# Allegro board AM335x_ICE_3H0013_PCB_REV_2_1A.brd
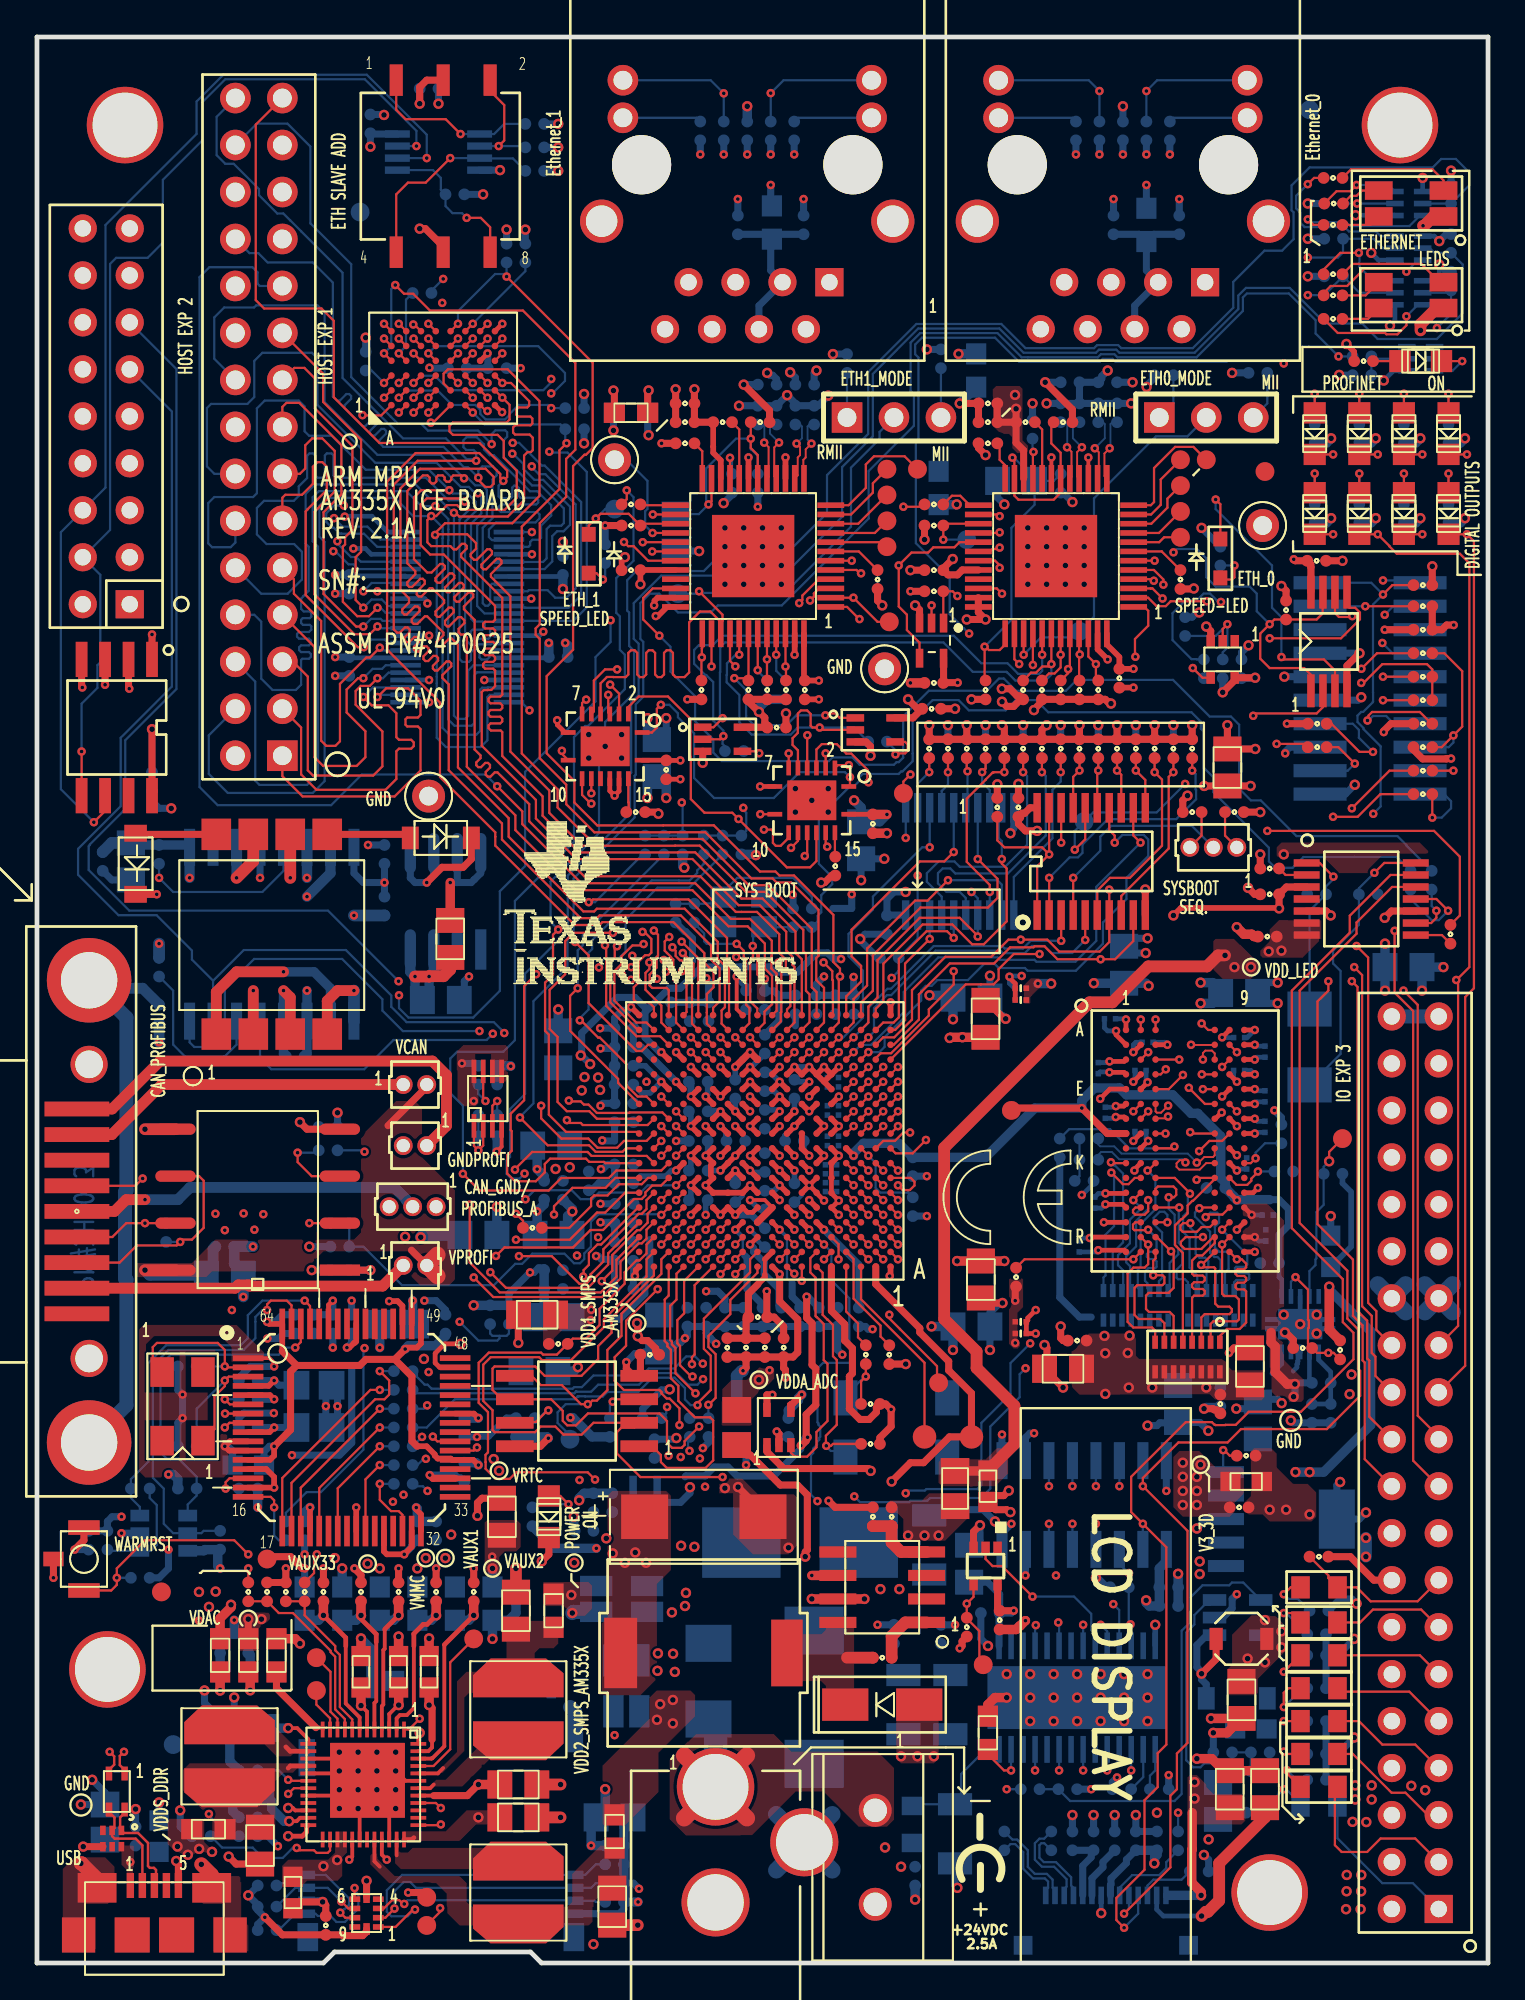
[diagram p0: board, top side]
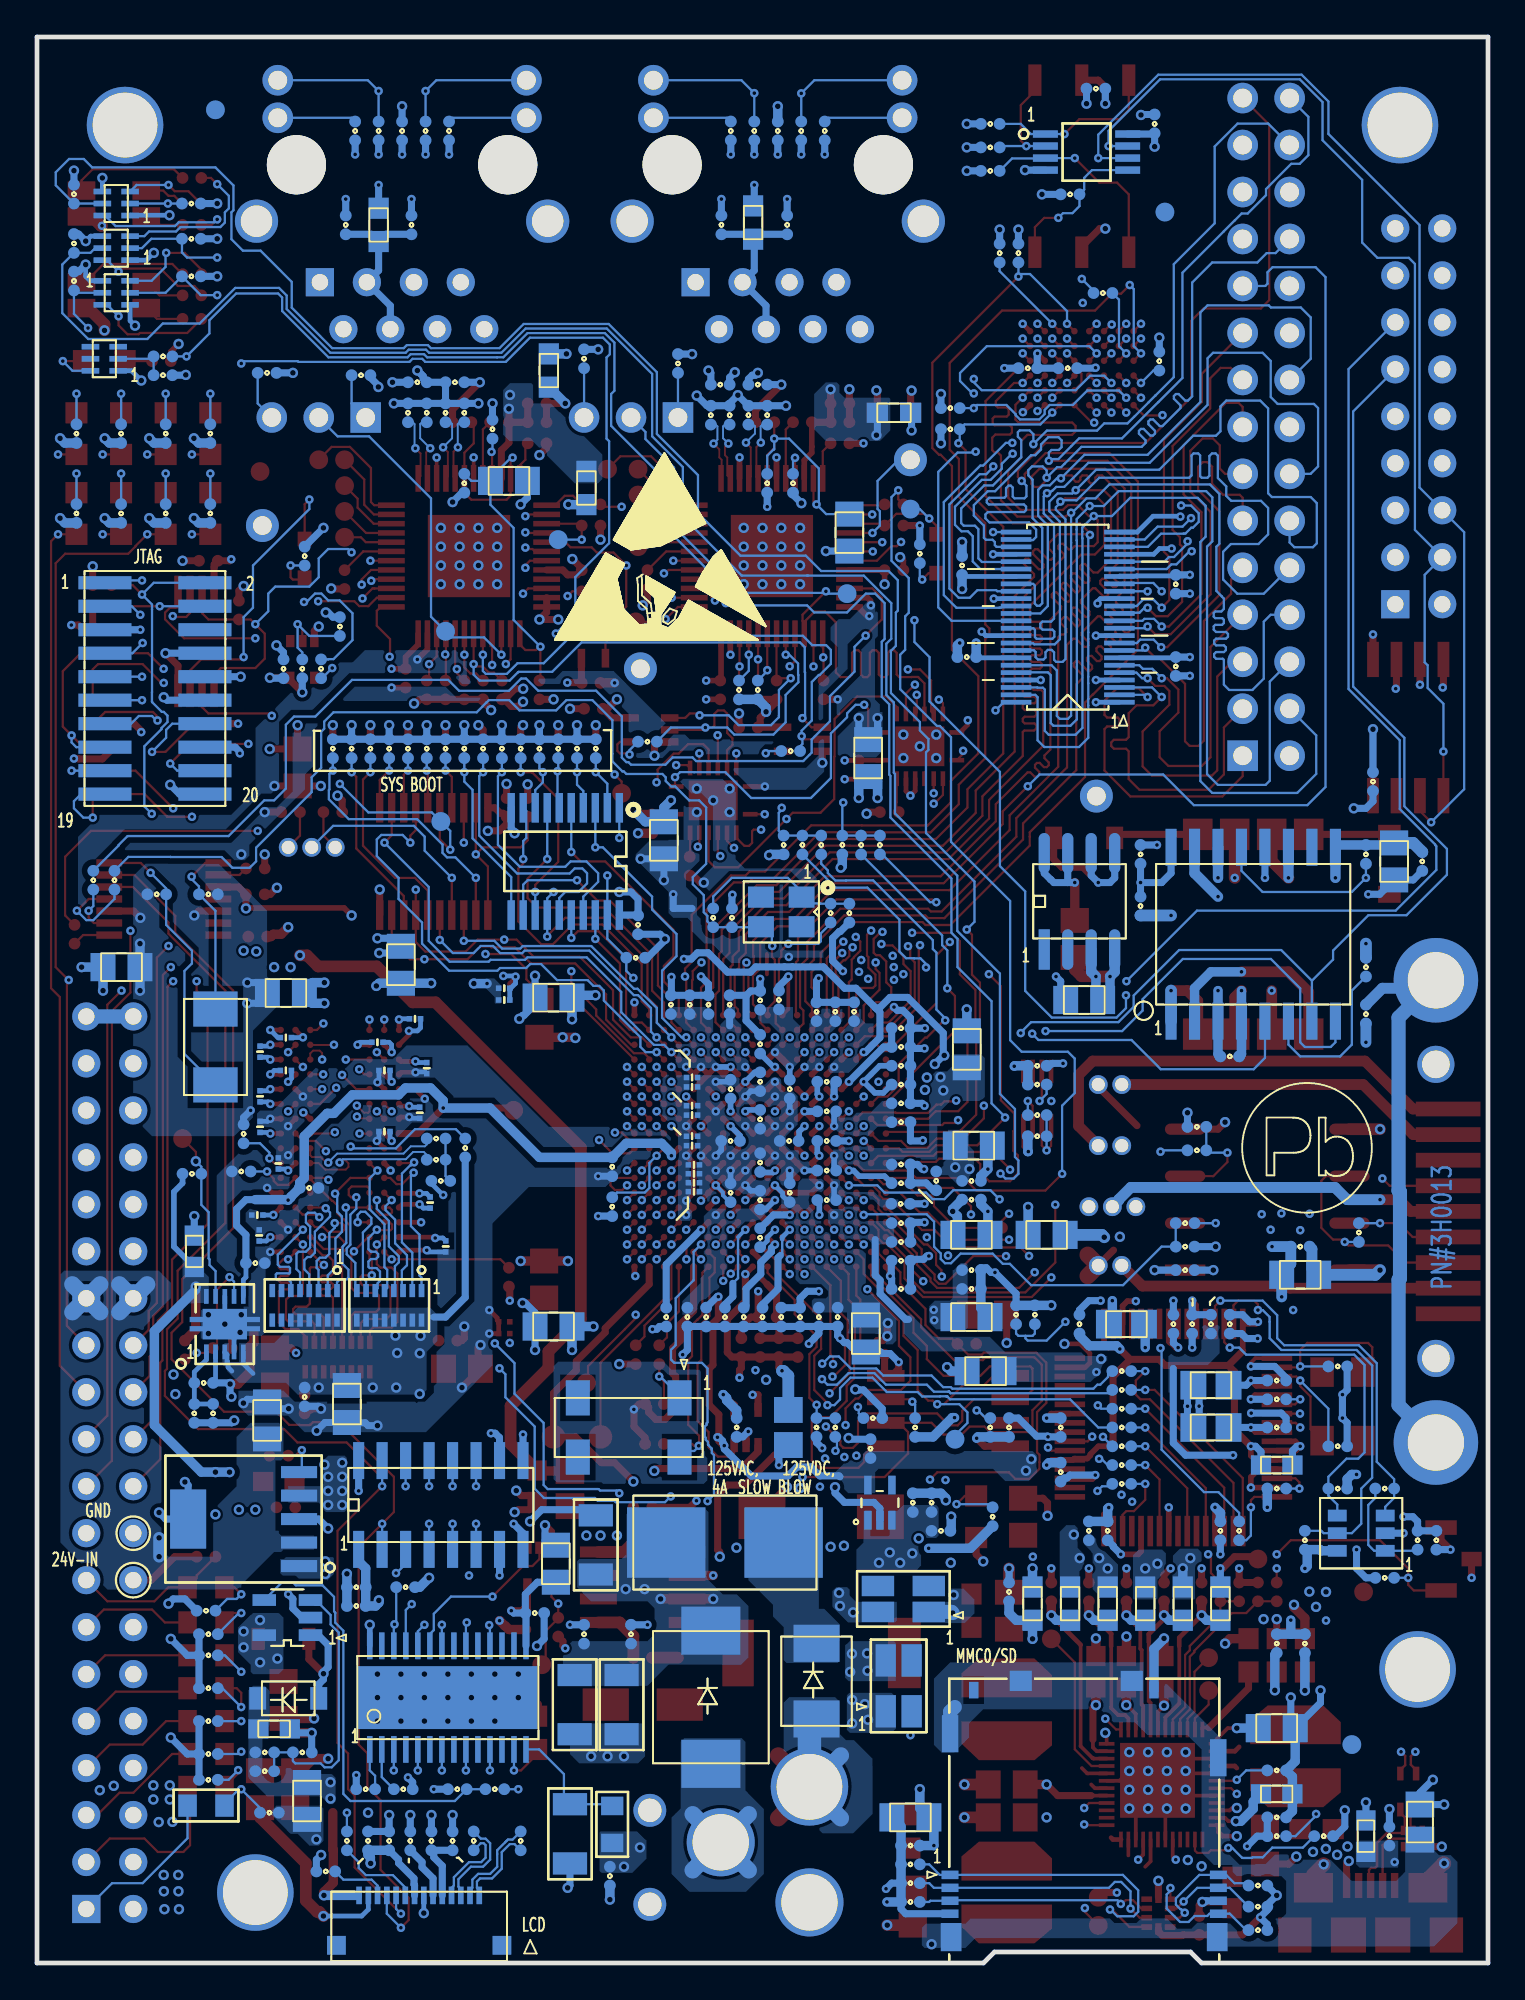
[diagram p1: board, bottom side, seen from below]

Outline 78.49 x 104.14 mm; copper layers: TOP, LYR2_GND, LYR3, LYR4, LYR5_PWR, BOTTOM. Coordinates in mm from the lower left corner of the outline.
Outline path: 0,104.14 0,0 15.49,0 16.09,0.6 26.7,0.6 27.29,0 78.49,0 78.49,104.14 0,104.14

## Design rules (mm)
net group C1: nets C1N C1P
net group C2: nets C2N C2P
net group MMC0_CLK: nets MMC0_CLK N28737675
net group PR_CLK: nets PR1_MDIO_MDCLK PR1_MII1_CLK
net group PRUETHER0_RD: nets PRUETHER0_RDN PRUETHER0_RDP
net group PRUETHER0_TD: nets PRUETHER0_TDN PRUETHER0_TDP
net group PRUETHER1_RD: nets PRUETHER1_RDN PRUETHER1_RDP
net group PRUETHER1_TD: nets PRUETHER1_TDN PRUETHER1_TDP
net group USB: nets USBDM USBDP
net group USB_FT: nets USBDM_FT USBDP_FT
net group 3W: nets CAN0_H CAN0_L PROFIBUS_A PROFIBUS_B SYS_RESETN UART0_RXD UART0_TXD UART1_RXD UART1_TXD UART3_RXD UART3_TXD
net group AIN: nets AIN1 AIN2 AIN3 AIN4 AIN5 AIN6 AIN7
net group CLK: nets AM335X_OSC0_IN AM335X_REFCLK_RMII1 AM335X_REFCLK_RMII2 ETH0_CLKIN ETH1_CLKIN MDIO_CLK OSC0_OUT OSC0_OUT1 OSC1_IN OSC1_OUT OSC1_OUT1 PRUETH0_RXCLK PRUETH0_TXCLK SPI0_SCLK SPI1_SCLK SYS_BOOT0 SYS_BOOT14 XTIN XTOUT
net group ETH_0: nets B_PRUETH0_LINKLED PRUETH0_ACTLED PRUETH0_COL PRUETH0_INT PRUETH0_JTCK PRUETH0_JTDI PRUETH0_JTDO PRUETH0_JTMS PRUETH0_JTRSTN PRUETH0_RESETN PRUETH0_RXERR PRUETH0_RXERR_COL PRUETH0_RXERR_COL_PROC PRUETH0_SPEEDLED PRUETH0_SWSTRAP
net group ETH_1: nets PRUETH1_ACTLED PRUETH1_COL PRUETH1_INTN PRUETH1_JTCK PRUETH1_JTDI PRUETH1_JTDO PRUETH1_JTMS PRUETH1_JTRSTN PRUETH1_RXD3 PRUETH1_RXDV PRUETH1_SPEEDLED PRUETH1_SWSTRAP PRUETH1_TXCLK PRUETH1_TXD0 PRUETH1_TXEN
net group GPMC_AD: nets GPMC_CSN0
net group PR1_MII0: nets PR1_MII0_RXLINK_SPEED PRUETH0_CRS PRUETH0_RXD0 PRUETH0_RXD1 PRUETH0_RXD2 PRUETH0_RXD3 PRUETH0_RXDV PRUETH0_TXD0 PRUETH0_TXD1 PRUETH0_TXD2 PRUETH0_TXD3 PRUETH0_TXEN SYS_BOOT1 SYS_BOOT2 SYS_BOOT3 SYS_BOOT4 SYS_BOOT5 SYS_BOOT6 SYS_BOOT7 SYS_BOOT8 SYS_BOOT9 SYS_BOOT10 SYS_BOOT11 SYS_BOOT12 SYS_BOOT13 SYS_BOOT15
net group PR1_MII1: nets PR1_MII1_COL_RMII2_CRS_DV PR1_MII1_CRS PRUETH1_LINKLED
net group PRUETH1_RXERR: nets PRUETH1_RXERR_COL
net group PWR: nets AGND_CAN AGND_PRUETH0 AGND_PRUETH1 AGNDFRAME_PRUETH0 AGNDFRAME_PRUETH1 BOOT CAN_GND/PROFIBUS_A CAP_VBB_MPU CAP_VDD_SRAM_CORE CAP_VDD_SRAM_MPU DDR_VREF GND_OSC0 GND_OSC1 GNDA_ADC GNDPROFI N17123334 N17123833 N21868977 N27955689 PROFI_GND PWR_SWIO PWR_VAUX1 PWR_VAUX2 PWR_VAUX33 PWR_VDAC PWR_VDD1_SMPS PWR_VDD2_SMPS PWR_VDDIO PWR_VDDS_DDR PWR_VDIG1 PWR_VDIG2 PWR_VMMC PWR_VPLL PWRON SENSE V3_3D_PROFIA V3_3D_PROFIB V3_3D_PRUETH0JCK V3_3D_PRUETH1JCK V5_0VOP VBAT_LCD VBREF VCOMH VDD_1V8FT VDD_FTREGIN VDD_FTVPHY VDD_FTVPLL VDD_RTC VDIG1 VPLL VPMIC_VRTC VPP VREFP_ADC
nets with their own width: min track width 0.305; nets VAUX1 VAUX33 VDD_LED VRTC

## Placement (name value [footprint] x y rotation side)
C1  0.01uF  [SM-7351-CAP-0402]  35.05 84.33 180 top
C2  0.01uF  [SM-7351-CAP-0402]  51.44 84.33 180 top
C3  0.01uF  [SM-7351-CAP-0402]  35.05 83.31 180 top
C4  0.1uF  [SM-7351-CAP-0402]  39.12 83.31 0 top
C5  0.01uF  [SM-7351-CAP-0402]  51.44 83.31 180 top
C6  0.1uF  [SM-7351-CAP-0402]  55.5 83.31 0 top
C7  0.1uF  [SM-7351-CAP-0402]  69.22 75.82 0 top
C8  0.01uF  [SM-7351-CAP-0402]  74.96 72.09 0 top
C9  0.01uF  [SM-7351-CAP-0402]  32.13 75.31 180 top
C10  0.01uF  [SM-7351-CAP-0402]  48.51 75.31 180 top
C11  0.01uF  [SM-7351-CAP-0402]  58.55 69.47 270 top
C12  0.01uF  [SM-7351-CAP-0402]  48.51 69.22 180 top
C13  0.1uF  [SM-7351-CAP-0402]  74.96 65.74 180 top
C14  0.1uF  [SM-7351-CAP-0402]  35.94 68.83 270 top
C15  0.01uF  [SM-7351-CAP-0402]  41.53 68.83 270 top
C16  0.1uF  [SM-7351-CAP-0402]  51.31 68.83 270 top
C17  0.1uF  [SM-7351-CAP-0402]  48.39 67.82 0 top
C18  0.1uF  [SM-7351-CAP-0402]  40.01 66.8 0 top
C19  0.1uF  [SM-7351-CAP-0402]  34.04 64.52 270 top
C20  0.1uF  [SM-7351-CAP-0402]  45.21 61.59 270 top
C21  0.1uF  [SM-7351-CAP-0402]  66.67 57.78 180 top
C22  0.1uF  [SM-7351-CAP-0402]  66.55 55.5 180 top
C23  10uF  [SM-7351-CAP-0805]  64.39 64.64 270 top
C24  4.7uF  [SM-7351-CAP-0805]  22.35 55.37 270 top
C25  0.1uF, 6.3V  [SMD0201]  53.21 52.7 0 top
C26  0.1uF, 6.3V  [SMD0201]  53.21 52.07 0 top
C27  10uF  [SM-7351-CAP-0805]  51.31 51.05 90 top
C28  10uF  [SM-7351-CAP-0805]  51.05 36.96 270 top
C29  10uF  [SM-7351-CAP-0805]  27.05 35.05 180 top
C30  0.1uF, 6.3V  [SMD0201]  53.21 34.67 0 top
C31  0.1uF, 6.3V  [SMD0201]  53.21 34.04 0 top
C32  0.1uF  [SM-7351-CAP-0402]  56.26 33.66 180 top
C33  0.001uF  [SM-7351-CAP-0402]  37.34 33.27 270 top
C34  0.01uF  [SM-7351-CAP-0402]  38.35 33.27 270 top
C35  0.01uF  [SM-7351-CAP-0402]  39.37 33.27 270 top
C36  0.01uF  [SM-7351-CAP-0402]  40.39 33.27 270 top
C37  0.01uF  [SM-7351-CAP-0402]  33.15 32.89 180 top
C38  10uF  [SM-7351-CAP-0805]  65.61 32.26 90 top
C39  10uF  [SM-7351-CAP-0805]  55.5 32.13 180 top
C40  22pF  [SM-7351-CAP-0402]  45.09 30.23 180 top
C41  0.1uF  [SM-7351-CAP-0402]  64.01 30.23 270 top
C42  22pF  [SM-7351-CAP-0402]  45.09 28.07 180 top
C43  0.01uF  [SM-7351-CAP-0402]  65.41 27.43 0 top
C44  4.7uF  [SM-7351-CAP-0603]  65.41 26.04 0 top
C45  4.7uF  [SM-7351-CAP-0603]  51.44 25.78 270 top
C46  0.01uF  [SM-7351-CAP-0402]  65.02 24.64 0 top
C47  10uF  [SM-7351-CAP-0805]  25.15 24.13 90 top
C48  47uF  [7343]  36.07 24.13 0 top
C49  2.2uF  [SM-7351-CAP-0402]  15.49 20.07 90 top
C50  2.2uF  [SM-7351-CAP-0402]  17.53 20.07 90 top
C51  2.2uF, 10V  [SM-7351-CAP-0402]  19.56 20.07 90 top
C52  2.2uF, 10V  [SM-7351-CAP-0402]  21.59 20.07 90 top
C53  2.2uF  [SM-7351-CAP-0402]  23.62 20.07 90 top
C54  10uF  [SM-7351-CAP-0805]  25.91 19.05 90 top
C55  0.1uF  [SM-7351-CAP-0402]  52.07 18.54 270 top
C56  0.01uF  [SM-7351-CAP-0402]  45.72 16.51 180 top
C57  4.7uF  [SM-7351-CAP-0603]  17.53 15.75 90 top
C58  4.7uF  [SM-7351-CAP-0603]  19.56 15.75 90 top
C59  4.7uF  [SM-7351-CAP-0603]  21.21 15.75 90 top
C60  2.2uF  [SM-7351-CAP-0805]  65.15 14.22 270 top
C61  10uF  [SM-7351-CAP-0805]  26.04 9.65 0 top
C62  2.2uF  [SM-7351-CAP-0805]  64.52 9.4 90 top
C63  2.2uF  [SM-7351-CAP-0805]  66.42 9.4 90 top
C64  10uF  [SM-7351-CAP-0805]  26.04 7.87 0 top
C65  10uF  [SM-7351-CAP-0805]  12.06 6.35 270 top
C66  4.7uF  [SM-7351-CAP-0603]  13.84 3.81 270 top
C67  10uF  [SM-7351-CAP-0805]  31.11 3.05 270 top
C68  0.01uF  [SM-7351-CAP-0402]  15.62 2.03 90 top
C69  0.01uF  [SM-7351-CAP-0402]  21.21 101.35 0 bottom
C70  0.1uF  [SM-7351-CAP-0402]  18.03 99.44 90 bottom
C71  0.1uF  [SM-7351-CAP-0402]  61.79 93.98 90 bottom
C72  0.1uF  [SM-7351-CAP-0402]  58.23 93.98 90 bottom
C73  0.1uF  [SM-7351-CAP-0402]  41.47 93.98 90 bottom
C74  0.1uF  [SM-7351-CAP-0402]  37.91 93.98 90 bottom
C75  0.1uF  [SM-7351-CAP-0402]  24.89 86.23 0 bottom
C76  1uF  [SM-7351-CAP-0402]  22.73 86.23 180 bottom
C77  0.1uF  [SM-7351-CAP-0402]  57.91 85.47 0 bottom
C78  0.1uF  [SM-7351-CAP-0402]  55.88 85.47 180 bottom
C79  0.1uF  [SM-7351-CAP-0402]  41.53 85.34 0 bottom
C80  0.1uF  [SM-7351-CAP-0402]  39.5 85.34 180 bottom
C81  10uF  [SM-7351-CAP-0805]  52.96 80.14 180 bottom
C82  0.1uF  [SM-7351-CAP-0402]  55.37 80.01 270 bottom
C83  0.1uF  [SM-7351-CAP-0402]  38.99 80.01 270 bottom
C84  10uF  [SM-7351-CAP-0805]  34.54 77.34 270 bottom
C85  0.1uF  [SM-7351-CAP-0402]  28.45 75.56 90 bottom
C86  0.1uF  [SM-7351-CAP-0402]  16.89 74.55 270 bottom
C87  0.1uF  [SM-7351-CAP-0402]  28.19 70.61 0 bottom
C88  0.1uF  [SM-7351-CAP-0402]  16.89 70.1 270 bottom
C89  18pF, 50V  [SM-7351-CAP-0402]  72.01 57.78 180 bottom
C90  18pF, 50V  [SM-7351-CAP-0402]  69.22 57.78 0 bottom
C91  0.1uF  [SM-7351-CAP-0402]  65.15 69.98 90 bottom
C92  10uF  [SM-7351-CAP-0805]  33.53 65.15 90 bottom
C93  0.1uF  [SM-7351-CAP-0402]  6.22 63.88 270 bottom
C94  10uF  [SM-7351-CAP-0805]  44.58 60.71 270 bottom
C95  10uF  [SM-7351-CAP-0805]  5.08 59.56 90 bottom
C96  0.1uF  [SM-7351-CAP-0402]  3.56 59.56 90 bottom
C97  2.2uF  [SM-7351-CAP-0805]  73.91 53.85 180 bottom
C98  0.01uF  [SM-7351-CAP-0402]  18.8 57.15 270 bottom
C99  24pF  [SM-7351-CAP-0402]  34.54 56.77 270 bottom
C100  24pF  [SM-7351-CAP-0402]  40.89 56.52 90 bottom
C101  10uF  [SM-7351-CAP-0805]  58.8 53.98 90 bottom
C102  10uF  [SM-7351-CAP-0805]  65.02 52.45 0 bottom
C103  0.1uF, 6.3V  [SMD0201]  53.21 52.7 0 bottom
C104  10uF  [SM-7351-CAP-0805]  50.55 52.2 0 bottom
C105  0.1uF, 6.3V  [SMD0201]  53.21 52.07 0 bottom
C106  0.01uF  [SM-7351-CAP-0402]  38.35 52.07 90 bottom
C107  10uF  [SM-7351-CAP-0805]  21.84 52.07 180 bottom
C108  0.01uF  [SM-7351-CAP-0402]  39.37 52.05 90 bottom
C109  0.01uF  [SM-7351-CAP-0402]  44.2 51.82 270 bottom
C110  0.01uF  [SM-7351-CAP-0402]  43.18 51.82 270 bottom
C111  0.01uF  [SM-7351-CAP-0402]  42.16 51.82 270 bottom
C112  0.01uF  [SM-7351-CAP-0402]  36.32 51.44 90 bottom
C113  0.01uF  [SM-7351-CAP-0402]  35.31 51.44 90 bottom
C114  0.01uF  [SM-7351-CAP-0402]  34.29 51.44 90 bottom
C115  0.1uF, 6.3V  [SMD0201]  58.04 51.05 180 bottom
C116  0.01uF  [SM-7351-CAP-0402]  31.75 50.55 180 bottom
C117  0.1uF, 6.3V  [SMD0201]  65.02 50.04 0 bottom
C118  0.1uF, 6.3V  [SMD0201]  60.07 49.78 0 bottom
C119  0.01uF  [SM-7351-CAP-0402]  39.37 49.68 270 bottom
C120  0.01uF  [SM-7351-CAP-0402]  31.75 49.53 180 bottom
C121  10uF  [SM-7351-CAP-0805]  28.19 49.4 270 bottom
C122  0.1uF, 6.3V  [SMD0201]  66.42 49.28 90 bottom
C123  0.01uF  [SM-7351-CAP-0402]  13.97 49.02 0 bottom
C124  0.01uF  [SM-7351-CAP-0402]  31.75 48.51 180 bottom
C125  0.01uF  [SM-7351-CAP-0402]  24.38 48.51 0 bottom
C126  0.1uF, 6.3V  [SMD0201]  57.4 48.39 270 bottom
C127  0.1uF, 6.3V  [SMD0201]  65.02 48.26 180 bottom
C128  0.1uF, 6.3V  [SMD0201]  59.69 48.26 0 bottom
C129  0.1uF, 6.3V  [SMD0201]  43.05 47.88 180 bottom
C130  0.01uF  [SM-7351-CAP-0402]  39.37 47.65 270 bottom
C131  0.01uF  [SM-7351-CAP-0402]  35.77 47.65 180 bottom
C132  0.01uF  [SM-7351-CAP-0402]  31.75 47.5 180 bottom
C133  0.1uF, 6.3V  [SMD0201]  43.05 47.37 180 bottom
C134  0.01uF  [SM-7351-CAP-0402]  40.97 47.25 90 bottom
C135  0.01uF  [SM-7351-CAP-0402]  37.77 47.25 270 bottom
C136  0.1uF, 6.3V  [SMD0201]  66.42 46.86 270 bottom
C137  0.01uF  [SM-7351-CAP-0402]  31.75 46.48 0 bottom
C138  0.1uF, 6.3V  [SMD0201]  43.05 46.35 180 bottom
C139  0.01uF  [SM-7351-CAP-0402]  35.77 46.05 0 bottom
C140  0.1uF, 6.3V  [SMD0201]  57.78 45.97 270 bottom
C141  0.1uF, 6.3V  [SMD0201]  43.05 45.85 180 bottom
C142  0.01uF  [SM-7351-CAP-0402]  39.37 45.62 270 bottom
C143  0.01uF  [SM-7351-CAP-0402]  31.75 45.47 0 bottom
C144  0.1uF, 6.3V  [SMD0201]  66.42 45.21 90 bottom
C145  100pF25V10%  [SM-7351-CAP-0402]  15.75 45.21 0 bottom
C146  0.1uF, 6.3V  [SMD0201]  59.69 44.96 0 bottom
C147  0.1uF, 6.3V  [SMD0201]  43.05 44.7 180 bottom
C148  0.01uF  [SM-7351-CAP-0402]  24.38 44.7 0 bottom
C149  0.01uF  [SM-7351-CAP-0402]  40.97 44.45 0 bottom
C150  0.01uF  [SM-7351-CAP-0402]  37.8 44.45 0 bottom
C151  0.01uF  [SM-7351-CAP-0402]  35.77 44.45 180 bottom
C152  0.01uF  [SM-7351-CAP-0402]  41.02 51.82 90 bottom
C153  0.1uF, 6.3V  [SMD0201]  43.05 44.2 180 bottom
C154  10uF  [SM-7351-CAP-0805]  27.81 44.2 180 bottom
C155  0.01uF  [SM-7351-CAP-0402]  39.37 43.28 90 bottom
C156  0.1uF, 6.3V  [SMD0201]  65.43 43.23 90 bottom
C157  0.01uF  [SM-7351-CAP-0402]  31.75 43.18 0 bottom
C158  0.1uF, 6.3V  [SMD0201]  42.95 43.16 180 bottom
C159  0.1uF  [SM-7351-CAP-0402]  47.37 43.05 270 bottom
C160  0.01uF  [SM-7351-CAP-0402]  35.77 42.85 180 bottom
C161  0.1uF, 6.3V  [SMD0201]  42.95 42.67 180 bottom
C162  0.1uF  [SM-7351-CAP-0402]  56.64 42.29 0 bottom
C163  0.01uF  [SM-7351-CAP-0402]  29.84 42.29 270 bottom
C164  0.01uF  [SM-7351-CAP-0402]  27.94 42.29 180 bottom
C165  0.1uF, 6.3V  [SMD0201]  42.95 42.19 180 bottom
C166  0.01uF  [SM-7351-CAP-0402]  31.75 42.16 180 bottom
C167  0.1uF  [SM-7351-CAP-0402]  63.77 41.91 180 bottom
C168  0.1uF, 6.3V  [SMD0201]  42.95 41.71 180 bottom
C169  0.01uF  [SM-7351-CAP-0402]  40.97 41.65 90 bottom
C170  0.01uF  [SM-7351-CAP-0402]  37.77 41.65 90 bottom
C171  0.01uF  [SM-7351-CAP-0402]  27.94 41.27 180 bottom
C172  0.01uF  [SM-7351-CAP-0402]  39.37 39.22 90 bottom
C173  0.01uF  [SM-7351-CAP-0402]  35.77 41.25 180 bottom
C174  0.1uF, 6.3V  [SMD0201]  57.22 41.12 90 bottom
C175  0.01uF  [SM-7351-CAP-0402]  31.77 41.05 0 bottom
C176  0.1uF, 6.3V  [SMD0201]  66.57 40.44 0 bottom
C177  0.01uF  [SM-7351-CAP-0402]  31.75 40.01 180 bottom
C178  10uF  [SM-7351-CAP-0805]  27.94 39.37 180 bottom
C179  10uF  [SM-7351-CAP-0805]  23.88 39.37 180 bottom
C180  0.1uF, 6.3V  [SMD0201]  66.47 39.34 90 bottom
C181  0.01uF  [SM-7351-CAP-0402]  39.37 41.25 90 bottom
C182  0.01uF  [SM-7351-CAP-0402]  31.75 38.99 180 bottom
C183  0.1uF, 6.3V  [SMD0201]  56.38 38.75 270 bottom
C184  100pF25V10%  [SM-7351-CAP-0402]  16.38 38.73 180 bottom
C185  0.1uF  [SM-7351-CAP-0402]  10.16 38.73 0 bottom
C186  4.7uF  [SM-7351-CAP-0603]  69.98 38.48 90 bottom
C187  0.01uF  [SM-7351-CAP-0402]  31.75 37.97 0 bottom
C188  0.1uF  [SM-7351-CAP-0402]  66.67 37.85 180 bottom
C189  0.01uF  [SM-7351-CAP-0402]  27.94 37.47 180 bottom
C190  0.01uF  [SM-7351-CAP-0402]  16.38 37.47 180 bottom
C191  4.7uF  [SM-7351-CAP-0805]  10.16 37.21 0 bottom
C192  0.01uF  [SM-7351-CAP-0402]  31.75 36.45 0 bottom
C193  0.01uF  [SM-7351-CAP-0402]  27.94 36.45 180 bottom
C194  0.01uF  [SM-7351-CAP-0402]  24.51 35.05 90 bottom
C195  1uF  [SM-7351-CAP-0402]  44.45 34.92 270 bottom
C196  0.01uF  [SM-7351-CAP-0402]  43.31 34.92 270 bottom
C197  0.01uF  [SM-7351-CAP-0402]  42.29 34.92 270 bottom
C198  1uF  [SM-7351-CAP-0402]  41.27 34.92 270 bottom
C199  1uF  [SM-7351-CAP-0402]  40.26 34.92 270 bottom
C200  1uF  [SM-7351-CAP-0402]  39.24 34.92 270 bottom
C201  0.01uF  [SM-7351-CAP-0402]  38.23 34.92 270 bottom
C202  0.01uF  [SM-7351-CAP-0402]  37.21 34.92 90 bottom
C203  0.01uF  [SM-7351-CAP-0402]  36.2 34.92 270 bottom
C204  0.01uF  [SM-7351-CAP-0402]  35.18 34.92 270 bottom
C205  10uF  [SM-7351-CAP-0805]  27.94 34.92 180 bottom
C206  0.1uF  [SM-7351-CAP-0402]  22.1 34.54 270 bottom
C207  0.1uF  [SM-7351-CAP-0402]  17.02 34.54 90 bottom
C208  0.1uF  [SM-7351-CAP-0402]  13.97 34.54 90 bottom
C209  10uF  [SM-7351-CAP-0805]  50.55 34.42 0 bottom
C210  10uF  [SM-7351-CAP-0805]  33.66 34.04 270 bottom
C211  18pF, 50V  [SM-7351-CAP-0402]  8.13 32.26 0 bottom
C212  10uF  [SM-7351-CAP-0805]  27.18 32 0 bottom
C213  0.1uF  [SM-7351-CAP-0402]  11.43 31.5 0 bottom
C214  0.1uF  [SM-7351-CAP-0402]  64.01 30.61 270 bottom
C215  10uF  [SM-7351-CAP-0805]  61.72 30.23 270 bottom
C216  0.001uF  [SM-7351-CAP-0402]  69.98 29.72 270 bottom
C217  2.2uF  [SM-7351-CAP-0805]  66.04 29.34 90 bottom
C218  0.01uF  [SM-7351-CAP-0402]  40.64 28.96 270 bottom
C219  0.01uF  [SM-7351-CAP-0402]  25.91 28.96 90 bottom
C220  0.1uF  [SM-7351-CAP-0402]  23.11 28.96 270 bottom
C221  0.1uF  [SM-7351-CAP-0402]  11.43 28.96 0 bottom
C222  18pF, 50V  [SM-7351-CAP-0402]  8.13 27.94 0 bottom
C223  1uF  [SM-7351-CAP-0402]  33.4 27.81 90 bottom
C224  4.7uF  [SM-7351-CAP-0603]  11.43 26.92 180 bottom
C225  0.1uF  [SM-7351-CAP-0402]  23.11 26.54 90 bottom
C226  1uF  [SM-7351-CAP-0402]  31.11 24.89 90 bottom
C227  0.1uF  [SM-7351-CAP-0402]  30.1 24.89 90 bottom
C228  1uF  [SM-7351-CAP-0402]  29.59 23.37 180 bottom
C229  0.01uF  [SM-7351-CAP-0402]  21.59 23.37 270 bottom
C230  0.1uF  [SM-7351-CAP-0402]  20.57 23.37 90 bottom
C231  0.1uF  [SM-7351-CAP-0402]  14.48 23.37 270 bottom
C232  0.1uF  [SM-7351-CAP-0402]  2.79 22.86 90 bottom
C233  10uF  [SM-7351-CAP-1206]  48.26 22.61 270 bottom
C234  2.2uF  [SM-7351-CAP-0805]  50.42 21.59 90 bottom
C235  1uF  [SM-7351-CAP-0402]  5.59 20.83 0 bottom
C236  0.01uF  [SM-7351-CAP-0402]  61.21 20.32 0 bottom
C237  2.2uF, 10V  [SM-7351-CAP-0402]  25.91 20.07 90 bottom
C238  1uF  [SM-7351-CAP-0402]  61.21 19.3 0 bottom
C239  0.022uF  [SM-7351-CAP-0402]  69.34 19.05 0 bottom
C240  0.01uF  [SM-7351-CAP-0402]  51.56 18.92 180 bottom
C241  0.022uF  [SM-7351-CAP-0402]  69.22 17.78 0 bottom
C242  0.1uF  [SM-7351-CAP-0402]  48.9 17.78 90 bottom
C243  0.1uF  [SM-7351-CAP-0402]  46.35 17.78 90 bottom
C244  2.2uF  [SM-7351-CAP-0402]  11.43 17.27 90 bottom
C245  2.2uF  [SM-7351-CAP-0402]  9.91 17.27 90 bottom
C246  0.022uF  [SM-7351-CAP-0402]  69.22 16.64 0 bottom
C247  0.022uF  [SM-7351-CAP-0402]  69.22 14.86 0 bottom
C248  10uF  [SM-7351-CAP-1206]  49.4 13.97 90 bottom
C249  10uF  [SM-7351-CAP-1206]  46.86 13.97 90 bottom
C250  0.022uF  [SM-7351-CAP-0402]  69.22 13.08 0 bottom
C251  10uF  [SM-7351-CAP-0805]  11.43 12.7 180 bottom
C252  1uF  [SM-7351-CAP-0603]  65.66 12.66 180 bottom
C253  0.022uF  [SM-7351-CAP-0402]  69.22 11.3 0 bottom
C254  0.01uF  [SM-7351-CAP-0402]  11.43 10.41 180 bottom
C255  10pF  [SM-7351-CAP-0402]  66.17 10.37 180 bottom
C256  0.022uF  [SM-7351-CAP-0402]  69.22 9.91 0 bottom
C257  4.7uF  [SM-7351-CAP-0603]  11.43 9.14 180 bottom
C258  2.2uF  [SM-7351-CAP-0805]  63.88 8.76 270 bottom
C259  0.022uF  [SM-7351-CAP-0402]  65.91 8.13 180 bottom
C260  10uF  [SM-7351-CAP-0805]  31.24 7.87 180 bottom
C261  2.2uF  [SM-7351-CAP-0402]  11.43 7.87 180 bottom
C262  10uF  [SM-7351-CAP-1206]  49.66 6.99 90 bottom
C263  4.7uF  [SM-7351-CAP-0603]  6.6 6.86 90 bottom
C264  0.01uF  [SM-7351-CAP-0402]  5.33 6.86 90 bottom
C265  0.1uF  [SM-7351-CAP-0402]  60.58 6.6 90 bottom
C266  1uF  [SM-7351-CAP-0402]  59.44 6.6 90 bottom
C267  0.022uF  [SM-7351-CAP-0402]  58.29 6.6 90 bottom
C268  1uF  [SM-7351-CAP-0402]  57.15 6.6 90 bottom
C269  0.1uF  [SM-7351-CAP-0402]  56.01 6.6 90 bottom
C270  1uF  [SM-7351-CAP-0402]  54.86 6.6 270 bottom
C271  1uF  [SM-7351-CAP-0402]  52.32 6.6 90 bottom
C272  0.1uF  [SM-7351-CAP-0402]  31.24 6.35 180 bottom
C273  0.001uF  [SM-7351-CAP-0402]  47.5 4.7 270 bottom
C275  0.01uF  [SM-7351-CAP-0402]  45.97 56.13 270 bottom
C277  0.01uF  [SM-7351-CAP-0402]  53.09 62.48 90 top
D1  Red_Green_Yellow_LED  [LED-SM1210]  74.33 95.14 180 top
D2  Red_Green_Yellow_LED  [LED-SM1210]  74.33 90.18 180 top
D3  Green LED  [SM_LED_0805]  74.84 86.62 0 top
D4  LED Yellow  [LEDLTST-S220]  64.01 75.95 270 top
D5  LED Yellow  [LEDLTST-S220]  29.84 76.2 270 top
D6  Green LED  [SM_LED_0805]  69.11 78.38 270 top
D7  Green LED  [SM_LED_0805]  71.52 78.38 270 top
D8  Green LED  [SM_LED_0805]  73.94 78.38 270 top
D9  Green LED  [SM_LED_0805]  76.35 78.38 270 top
D10  Green LED  [SM_LED_0805]  69.11 82.69 270 top
D11  MBR0520LT1  [MBR0520L]  21.84 60.83 0 top
D12  Green LED  [SM_LED_0805]  71.52 82.69 270 top
D13  MBR0520LT1  [MBR0520L]  5.33 59.44 270 top
D14  Green LED  [SM_LED_0805]  73.94 82.69 270 top
D15  Green LED  [SM_LED_0805]  76.35 82.69 270 top
D16  Green LED  [SM_LED_0805]  27.69 24.13 270 top
D17  B340A-13-F  [DO157LS_116X220SMA]  45.72 13.97 0 top
D18  -  [MBRS140T]  36.32 15.24 270 bottom
D19  SMCJ26CA  [SMCJ36CA]  42.04 14.37 270 bottom
D20  MBR0520LT1  [MBR0520L]  64.9 14.31 0 bottom
F1  Fuse 4A  [SMDFUSEBLK]  41.27 22.73 0 bottom
FB2  150OHM800mA  [SM-7351-IND-0805]  37.85 28.96 270 top
FB3  150OHM800mA  [SM-7351-IND-0805]  49.66 25.65 270 top
FB9  150OHM800mA  [SM-7351-IND-0805]  19.56 34.54 0 bottom
FB10  150OHM800mA  [SM-7351-IND-0805]  14.99 31.24 180 bottom
FB11  150OHM800mA  [SM-7351-IND-0805]  37.85 28.96 270 bottom
FB12  150OHM800mA  [SM-7351-IND-0805]  14.99 28.96 180 bottom
FB13  150OHM800mA  [SM-7351-IND-0805]  3.68 7.62 270 bottom
J1  RJ-45 10_100Mb  [CNRJ45-1X1WLED]  42.86 90.88 180 top
J2  RJ-45 10_100Mb  [CNRJ45-1X1WLED]  63.18 90.88 180 top
J3  Header 9x2 Female  [HDR2X9VER_335M]  5.02 73.47 90 top
J4  Header 15x2 Female  [HDR2X15-344M]  13.27 65.28 90 top
J5  TMS-103-01  [SIP3_50LS]  62.36 60.33 90 top
J6  TMS-102-01  [SIP2_50LS]  19.81 47.5 90 top
J7  TMS-102-01  [SIP2_50LS]  21.08 44.2 270 top
J8  TMS-103-01  [SIP3_50LS]  21.59 40.89 270 top
J9  Conn_DB9F  [NORCOMP_DB9F_SMD]  2.16 40.64 90 top
J10  TMS-102-01  [SIP2_50LS]  19.81 37.72 90 top
J11  Power Jack RAPC722X  [CNRAPC722]  36.7 9.53 0 top
J12  Connector_Screwdown  [CONN_OSTTC02]  45.34 8.26 270 top
J13  USB_MicroAB  [ZX62-AB-5PA]  6.35 4.19 0 top
J14  Header 20x2 Female  [HDR2X20-335M]  75.82 2.92 90 top
J15  CTI JTAG  [HEADER10X2]  72.11 68.92 270 bottom
J16  SCHA5B0200  [SD-MICRO-SCHA5B0300]  21.84 4.76 180 bottom
J17  10051922-1410ELF  [CON14_P5MM_3P75X9P5SMD]  57.81 1.98 90 bottom
J18  HEADER 3  [HEADER_3X1]  60.71 83.57 0 top
J19  HEADER 3  [HEADER_3X1]  43.81 83.57 0 top
L1  DA2304-AL  [DA2304]  12.7 55.63 90 top
L2  2.2uH  [IND108SMD_110X102]  65.15 17.53 180 top
L3  68uH  [IND_354SMD_400SQ]  36.07 16.76 180 top
L4  2.2uH  [VLCF5020T]  26.04 13.72 90 top
L5  2.2uH  [VLCF5020T]  10.41 11.18 270 top
L6  ACM2012  [ACM2012H]  4.32 9.27 270 top
L7  2.2uH  [VLCF5020T]  26.04 3.81 270 top
MH1  3.5MM_MHOLE  [MH163X138PL]  4.76 99.38 0 top
MH2  3.5MM_MHOLE  [MH163X138PL]  73.72 99.38 0 top
MH3  3.5MM_MHOLE  [MH163X138PL]  3.81 15.88 0 top
MH4  3MM_MHOLE  [MH163X138PL]  66.67 3.81 0 top
NOREF  -  []  26.7 0.6 0 top
NOREF#2  -  []  15.49 0 0 top
NOREF#3  -  []  -366.46 -233.81 0 top
NOREF#4  -  []  16.09 0.6 0 top
NOREF#5  -  []  15.87 0.18 0 top
NOREF#6  -  []  0 0 0 top
NOREF#7  -  []  0 0 0 top
NOREF#8  -  []  0 104.14 0 top
NOREF#9  -  []  0 -10.69 0 top
NOREF#10  -  []  0 0 0 top
NOREF#11  -  [unnamed#2]  66.42 80.64 270 top
NOREF#12  -  []  78.49 0 90 top
NOREF#13  -  []  16.09 0.6 0 top
NOREF#14  -  [unnamed#2]  6.73 20.07 270 top
NOREF#15  -  []  78.49 0 90 top
NOREF#16  -  []  27.29 0 0 top
NOREF#17  -  [unnamed#2]  68.83 100.2 0 bottom
NOREF#18  -  [unnamed#2]  17.48 94.67 270 bottom
NOREF#19  -  [unnamed#2]  7.37 11.81 270 bottom
Q1  DMC564040R  [SMINI6-F3-B]  74.2 95.14 270 bottom
Q2  DMC564040R  [SMINI6-F3-B]  74.2 92.72 270 bottom
Q3  DMC564040R  [SMINI6-F3-B]  74.2 90.31 90 bottom
Q4  DMC564040R  [SMINI6-F3-B]  74.84 86.74 270 bottom
R1  330  [SM-7351-RES-0402]  70.1 96.52 0 top
R2  330  [SM-7351-RES-0402]  70.14 95.14 0 top
R3  330  [SM-7351-RES-0402]  70.1 93.98 0 top
R4  330  [SM-7351-RES-0402]  70.1 91.31 0 top
R5  330  [SM-7351-RES-0402]  70.1 90.17 0 top
R6  330  [SM-7351-RES-0402]  70.1 88.9 0 top
R7  2.2K  [SM-7351-RES-0402]  37.08 83.31 0 top
R8  2.2K  [SM-7351-RES-0402]  53.47 83.31 0 top
R9  4.87K  [SM-7351-RES-0402]  35.05 82.17 0 top
R10  4.87K  [SM-7351-RES-0402]  51.44 82.17 0 top
R11  10K, 1%  [SM-7351-RES-0402]  67.56 73.15 270 top
R12  33  [SM-7351-RES-0402]  32.13 78.87 180 top
R13  33  [SM-7351-RES-0402]  48.51 78.87 180 top
R14  4.7K  [SM-7351-RES-0402]  74.96 74.5 180 top
R15  2.2K  [SM-7351-RES-0402]  32.13 77.72 180 top
R16  2.2K  [SM-7351-RES-0402]  48.51 77.72 180 top
R17  0  [SM-7351-RES-0402]  74.96 73.36 180 top
R18  2.2K  [SM-7351-RES-0402]  45.47 74.8 270 top
R19  2.2K  [SM-7351-RES-0402]  61.85 74.8 270 top
R20  100, 1%  [SM-7351-RES-0402]  74.96 70.82 180 top
R21  10K  [SM-7351-RES-0402]  48.51 74.17 180 top
R22  0  [SM-7351-RES-0402]  74.96 69.55 0 top
R23  0  [SM-7351-RES-0402]  74.96 68.28 0 top
R24  4.7K  [SM-7351-RES-0402]  69.25 67.01 180 top
R25  4.7K  [SM-7351-RES-0402]  74.96 67.01 180 top
R26  0  [SM-7351-RES-0402]  69.25 65.74 0 top
R27  2.2K  [SM-7351-RES-0402]  38.48 68.83 270 top
R28  2.2K  [SM-7351-RES-0402]  39.5 68.83 270 top
R29  2.2K  [SM-7351-RES-0402]  40.51 68.83 270 top
R30  2.2K  [SM-7351-RES-0402]  53.34 68.83 270 top
R31  2.2K  [SM-7351-RES-0402]  54.36 68.83 270 top
R32  2.2K  [SM-7351-RES-0402]  55.37 68.83 270 top
R33  2.2K  [SM-7351-RES-0402]  56.39 68.83 270 top
R34  2.2K  [SM-7351-RES-0402]  57.4 68.83 270 top
R35  0  [SM-7351-RES-0402]  74.96 64.47 180 top
R36  0  [SM-7351-RES-0402]  74.96 63.2 180 top
R37  10K, 1%  [SM-7351-RES-0402]  62.48 62.23 180 top
R38  100K  [SM-7351-RES-0402]  64.77 62.23 180 top
R39  4.7K  [SM-7351-RES-0402]  66.67 59.18 180 top
R40  1K  [SM-7351-RES-0402]  32.38 62.23 180 top
R41  1K  [SM-7351-RES-0402]  43.18 59.31 90 top
R42  33  [SM-7351-RES-0402]  76.45 55.63 90 top
R43  100K  [SM-7351-RES-0402]  53.34 65.66 90 top
R44  10K, 1%  [SM-7351-RES-0402]  54.36 65.66 90 top
R45  10K, 1%  [SM-7351-RES-0402]  51.31 65.66 90 top
R46  100K  [SM-7351-RES-0402]  52.32 65.66 90 top
R47  100K  [SM-7351-RES-0402]  50.29 65.66 90 top
R48  100K  [SM-7351-RES-0402]  55.37 65.66 90 top
R49  100K  [SM-7351-RES-0402]  49.28 65.66 90 top
R50  10K, 1%  [SM-7351-RES-0402]  48.26 65.66 90 top
R51  100K  [SM-7351-RES-0402]  56.39 65.66 90 top
R52  100K  [SM-7351-RES-0402]  57.4 65.66 90 top
R53  100K  [SM-7351-RES-0402]  58.42 65.66 90 top
R54  10K, 1%  [SM-7351-RES-0402]  59.44 65.66 90 top
R55  10K, 1%  [SM-7351-RES-0402]  61.47 65.66 90 top
R56  100K  [SM-7351-RES-0402]  60.45 65.66 90 top
R57  100K  [SM-7351-RES-0402]  62.48 65.66 90 top
R58  22  [SM-7351-RES-0402]  26.8 39.75 0 top
R59  1K  [SM-7351-RES-0402]  52.96 37.08 90 top
R60  0  [SM-7351-RES-0402]  38.99 34.92 0 top
R61  2.2K  [SM-7351-RES-0402]  28.19 33.48 180 top
R62  10K, 1%  [SM-7351-RES-0402]  68.46 33.25 0 top
R63  10K, 1%  [SM-7351-RES-0402]  70.48 33.15 90 top
R64  0  [SM-7351-RES-0402]  44.83 32.89 270 top
R65  10K  [SM-7351-RES-0402]  46.1 32.89 270 top
R66  3.24K  [SM-7351-RES-0402]  45.21 24.13 270 top
R67  10K  [SM-7351-RES-0402]  46.23 24.13 90 top
R68  1.2K, MELF  [SMD_MELF0102]  69.35 20.31 180 top
R69  0  [SM-7351-RES-0402]  11.43 20.07 90 top
R70  4.7K  [SM-7351-RES-0402]  12.45 20.07 90 top
R71  4.7K  [SM-7351-RES-0402]  13.46 20.07 90 top
R72  0  [SM-7351-RES-0402]  14.48 20.07 90 top
R73  0  [SM-7351-RES-0603]  27.94 19.05 270 top
R74  1.2K, MELF  [SMD_MELF0102]  69.34 18.41 180 top
R75  10K  [SM-7351-RES-0402]  50.29 18.16 270 top
R76  0  [SM-7351-RES-0603]  9.91 16.64 90 top
R77  0  [SM-7351-RES-0603]  11.43 16.64 90 top
R78  0  [SM-7351-RES-0603]  12.95 16.64 270 top
R79  1.2K, MELF  [SMD_MELF0102]  69.34 16.64 180 top
R80  1.2K, MELF  [SMD_MELF0102]  69.34 14.86 180 top
R81  1.2K, MELF  [SMD_MELF0102]  69.34 13.08 180 top
R82  25K  [SM-7351-RES-0603]  51.44 12.45 270 top
R83  1.2K, MELF  [SMD_MELF0102]  69.34 11.3 180 top
R84  1.2K, MELF  [SMD_MELF0102]  69.34 9.53 180 top
R85  0  [SM-7351-RES-0603]  9.27 7.24 0 top
R86  0  [SM-7351-RES-0603]  31.24 7.11 270 top
R87  1K  [SM-7351-RES-0402]  22.61 95.63 180 bottom
R88  1K  [SM-7351-RES-0402]  26.92 99.44 180 bottom
R89  330  [SM-7351-RES-0402]  56.2 99.06 270 bottom
R90  2.2K  [SM-7351-RES-0402]  57.47 99.06 270 bottom
R91  0  [SM-7351-RES-0402]  58.74 99.06 270 bottom
R92  2.2K  [SM-7351-RES-0402]  60.01 99.06 270 bottom
R93  330  [SM-7351-RES-0402]  61.28 99.06 270 bottom
R94  330  [SM-7351-RES-0402]  35.88 99.06 270 bottom
R95  2.2K  [SM-7351-RES-0402]  37.15 99.06 270 bottom
R96  0  [SM-7351-RES-0402]  38.42 99.06 270 bottom
R97  2.2K  [SM-7351-RES-0402]  39.69 99.06 270 bottom
R98  330  [SM-7351-RES-0402]  40.96 99.06 270 bottom
R99  1K  [SM-7351-RES-0402]  26.92 98.17 180 bottom
R100  1K  [SM-7351-RES-0402]  26.92 96.9 180 bottom
R101  10K  [SM-7351-RES-0402]  26.42 92.46 90 bottom
R102  1K  [SM-7351-RES-0402]  25.4 92.46 270 bottom
R103  1K  [SM-7351-RES-0402]  76.49 95.64 270 bottom
R104  1K  [SM-7351-RES-0402]  70.14 95.14 0 bottom
R105  0  [SM-7351-RES-0402]  20.83 90.3 180 bottom
R106  1K  [SM-7351-RES-0402]  70.14 93.23 0 bottom
R107  1K  [SM-7351-RES-0402]  76.49 92.98 270 bottom
R108  1K  [SM-7351-RES-0402]  70.14 91.2 0 bottom
R109  1K  [SM-7351-RES-0402]  76.49 90.94 270 bottom
R110  2.2K  [SM-7351-RES-0402]  48.9 86.74 270 bottom
R111  10K  [SM-7351-RES-0402]  17.78 86.61 90 bottom
R112  2.2K  [SM-7351-RES-0402]  43.81 86.49 270 bottom
R113  2.2K  [SM-7351-RES-0402]  66.04 85.98 0 bottom
R114  2.2K  [SM-7351-RES-0402]  60.96 85.85 0 bottom
R115  1K  [SM-7351-RES-0402]  29.08 84.07 180 bottom
R116  49.9  [SM-7351-RES-0402]  58.42 83.82 270 bottom
R117  49.9  [SM-7351-RES-0402]  57.4 83.82 270 bottom
R118  49.9  [SM-7351-RES-0402]  56.39 83.82 270 bottom
R119  49.9  [SM-7351-RES-0402]  55.37 83.82 270 bottom
R120  49.9  [SM-7351-RES-0402]  42.04 83.69 270 bottom
R121  49.9  [SM-7351-RES-0402]  41.02 83.69 270 bottom
R122  49.9  [SM-7351-RES-0402]  40.01 83.69 270 bottom
R123  49.9  [SM-7351-RES-0402]  38.99 83.69 270 bottom
R124  2.2K  [SM-7351-RES-0402]  53.85 82.93 90 bottom
R125  10K  [SM-7351-RES-0402]  29.08 82.93 0 bottom
R126  0  [SM-7351-RES-0402]  71.67 86.87 180 bottom
R127  1K  [SM-7351-RES-0402]  71.67 85.85 0 bottom
R128  330  [SM-7351-RES-0402]  71.75 86.61 180 top
R129  2.2K  [SM-7351-RES-0402]  37.59 80.01 270 bottom
R130  330  [SM-7351-RES-0402]  64.01 76.07 90 bottom
R131  330  [SM-7351-RES-0402]  30.73 76.2 90 bottom
R132  150  [SM-7351-RES-0402]  69.11 78.38 90 bottom
R133  150  [SM-7351-RES-0402]  71.52 78.38 90 bottom
R134  2.2K  [SM-7351-RES-0402]  40.51 68.83 270 bottom
R135  2.2K  [SM-7351-RES-0402]  39.5 68.83 270 bottom
R136  150  [SM-7351-RES-0402]  73.94 78.38 90 bottom
R137  4.7K  [SM-7351-RES-0402]  62.1 72.26 270 bottom
R138  0  [SM-7351-RES-0402]  45.47 66.04 180 bottom
R139  0  [SM-7351-RES-0402]  37.72 65.53 180 bottom
R140  150  [SM-7351-RES-0402]  76.35 78.38 90 bottom
R141  10K  [SM-7351-RES-0402]  64.14 69.98 270 bottom
R142  0  [SM-7351-RES-0402]  63.12 69.98 270 bottom
R143  150  [SM-7351-RES-0402]  69.11 82.69 90 bottom
R144  33  [SM-7351-RES-0402]  74.3 58.55 90 bottom
R145  2.2K  [SM-7351-RES-0402]  38.1 60.45 270 bottom
R146  0  [SM-7351-RES-0402]  37.08 60.45 270 bottom
R147  0  [SM-7351-RES-0402]  36.07 60.45 270 bottom
R148  2.2K  [SM-7351-RES-0402]  34.92 60.45 270 bottom
R149  0  [SM-7351-RES-0402]  33.91 60.45 270 bottom
R150  0  [SM-7351-RES-0402]  32.89 60.45 270 bottom
R151  150  [SM-7351-RES-0402]  71.52 82.69 90 bottom
R152  100K  [SM-7351-RES-0402]  18.8 59.94 270 bottom
R153  100K  [SM-7351-RES-0402]  6.6 59.94 270 bottom
R154  33  [SM-7351-RES-0402]  75.44 58.55 90 bottom
R155  150  [SM-7351-RES-0402]  73.94 82.69 90 bottom
R156  0  [SM-7351-RES-0402]  35.56 56.77 90 bottom
R157  100K  [SM-7351-RES-0402]  62.48 65.66 270 bottom
R158  100K  [SM-7351-RES-0402]  60.45 65.66 270 bottom
R159  100K  [SM-7351-RES-0402]  61.47 65.66 270 bottom
R160  100K  [SM-7351-RES-0402]  59.44 65.66 270 bottom
R161  100K  [SM-7351-RES-0402]  58.42 65.66 270 bottom
R162  100K  [SM-7351-RES-0402]  57.4 65.66 270 bottom
R163  100K  [SM-7351-RES-0402]  56.39 65.66 270 bottom
R164  100K  [SM-7351-RES-0402]  48.26 65.66 270 bottom
R165  100K  [SM-7351-RES-0402]  49.28 65.66 270 bottom
R166  100K  [SM-7351-RES-0402]  55.37 65.66 270 bottom
R167  100K  [SM-7351-RES-0402]  50.29 65.66 270 bottom
R168  100K  [SM-7351-RES-0402]  52.32 65.66 270 bottom
R169  100K  [SM-7351-RES-0402]  51.31 65.66 270 bottom
R170  100K  [SM-7351-RES-0402]  54.36 65.66 270 bottom
R171  100K  [SM-7351-RES-0402]  53.34 65.66 270 bottom
R172  1M  [SM-7351-RES-0402]  41.91 56.52 270 bottom
R173  150  [SM-7351-RES-0402]  76.35 82.69 90 bottom
R174  2.2K  [SM-7351-RES-0402]  6.6 53.85 270 bottom
R175  0  [SM-7351-RES-0402]  6.6 51.31 270 bottom
R176  100K  [SM-7351-RES-0402]  24.38 47.5 180 bottom
R177  1K  [SM-7351-RES-0402]  24.38 45.85 180 bottom
R178  10K, 1%  [SM-7351-RES-0402]  67.31 44.83 270 bottom
R179  33  [SM-7351-RES-0402]  56.9 44.58 180 bottom
R180  33  [SM-7351-RES-0402]  55.32 44.07 270 bottom
R181  33  [SM-7351-RES-0402]  15.75 43.94 180 bottom
R182  33  [SM-7351-RES-0402]  56.9 43.43 180 bottom
R183  240, 1%  [SM-7351-RES-0402]  67.44 42.8 180 bottom
R184  10K, 1%  [SM-7351-RES-0402]  70.1 42.67 0 bottom
R185  49.9  [SM-7351-RES-0402]  47.37 40.89 90 bottom
R186  33  [SM-7351-RES-0402]  16.38 40.01 180 bottom
R187  10K  [SM-7351-RES-0402]  25.53 35.05 270 bottom
R188  10K, 1%  [SM-7351-RES-0402]  16 34.54 90 bottom
R189  4.75K, 1%  [SM-7351-RES-0402]  14.99 34.54 270 bottom
R190  0  [SM-7351-RES-0402]  19.81 32 180 bottom
R191  10K, 1%  [SM-7351-RES-0402]  69.47 31.37 180 bottom
R192  0  [SM-7351-RES-0402]  19.81 30.99 180 bottom
R193  12.1K, 1%  [SM-7351-RES-0402]  11.43 30.48 180 bottom
R194  0  [SM-7351-RES-0402]  19.81 29.97 180 bottom
R195  10K, 1%  [SM-7351-RES-0402]  68.96 29.72 90 bottom
R196  2.2K  [SM-7351-RES-0402]  33.27 29.46 180 bottom
R197  10K  [SM-7351-RES-0402]  36.32 28.96 270 bottom
R198  0  [SM-7351-RES-0402]  35.31 28.96 90 bottom
R199  10K  [SM-7351-RES-0402]  30.99 28.96 270 bottom
R200  10K  [SM-7351-RES-0402]  26.92 28.96 270 bottom
R201  0  [SM-7351-RES-0402]  19.81 28.96 180 bottom
R202  0  [SM-7351-RES-0402]  19.81 27.94 180 bottom
R203  0  [SM-7351-RES-0402]  19.81 26.92 180 bottom
R204  0  [SM-7351-RES-0402]  19.81 25.91 180 bottom
R205  2.2K  [SM-7351-RES-0402]  11.43 25.65 0 bottom
R206  10K  [SM-7351-RES-0402]  8.13 25.65 180 bottom
R207  2.2K  [SM-7351-RES-0402]  5.59 25.65 0 bottom
R208  150  [SM-7351-RES-0402]  26.8 24.13 270 bottom
R209  0  [SM-7351-RES-0402]  13.46 23.37 270 bottom
R210  10K  [SM-7351-RES-0402]  9.91 22.86 270 bottom
R211  10K  [SM-7351-RES-0402]  3.81 22.86 90 bottom
R212  0.05ohm1% Sense  [SM_RES_LVK12]  31.62 19.68 0 bottom
R213  0  [SM-7351-RES-0603]  24.64 19.43 90 bottom
R214  0  [SM-7351-RES-0603]  22.61 19.43 90 bottom
R215  0  [SM-7351-RES-0603]  20.57 19.43 270 bottom
R216  0  [SM-7351-RES-0603]  18.54 19.43 270 bottom
R217  0  [SM-7351-RES-0603]  16.51 19.43 270 bottom
R218  0  [SM-7351-RES-0603]  14.48 19.43 270 bottom
R219  0.05ohm1% Sense  [SM_RES_LVK12]  31.88 14.99 90 bottom
R220  1.62M  [SM-7351-RES-0402]  66.17 11.39 0 bottom
R221  180K  [SM-7351-RES-0402]  64.14 11.39 0 bottom
R222  0  [SM-7351-RES-0402]  60.71 9.4 180 bottom
R223  0  [SM-7351-RES-0402]  58.67 9.4 0 bottom
R224  0  [SM-7351-RES-0402]  55.75 9.4 180 bottom
R225  0  [SM-7351-RES-0402]  53.72 9.4 180 bottom
R226  1.2K, MELF  [SMD_MELF0102]  69.34 8.51 180 bottom
R227  49.9  [SMD_MELF0102]  47.37 7.49 270 bottom
R228  0  [SM-7351-RES-0402]  11.43 6.86 0 bottom
R229  0  [SM-7351-RES-0402]  8.89 6.86 180 bottom
R230  0  [SM-7351-RES-0402]  61.72 6.6 270 bottom
R231  10K  [SM-7351-RES-0402]  31.24 5.33 0 bottom
R232  392K  [SM-7351-RES-0402]  62.87 4.95 0 bottom
R233  10K  [SM-7351-RES-0402]  31.24 4.32 0 bottom
R234  10K  [SM-7351-RES-0402]  12.45 4.19 180 bottom
R235  10K  [SM-7351-RES-0402]  31.24 3.3 0 bottom
R236  10K  [SM-7351-RES-0402]  12.45 3.05 180 bottom
R237  10K  [SM-7351-RES-0402]  12.45 1.78 180 bottom
R238  120  [SM-7351-RES-0402]  6.99 39.5 270 bottom
R239  0  [SM-7351-RES-0603]  32.13 83.82 180 top
R240  0  [SM-7351-RES-0603]  32.13 83.82 180 bottom
R241  0  [SM-7351-RES-0603]  48.77 79.76 270 bottom
R242  0  [SM-7351-RES-0603]  50.8 86.11 90 bottom
R243  2.2K  [SM-7351-RES-0402]  69.34 21.97 180 top
R244  2.2K  [SM-7351-RES-0402]  58.55 20.32 180 bottom
R277  4.7K  [SM-7351-RES-0402]  46.1 54.36 0 bottom
R278  4.7K  [SM-7351-RES-0402]  51.94 62.48 270 top
R279  0  [SM-7351-RES-0603]  39.75 94.11 270 bottom
R280  0  [SM-7351-RES-0603]  60.01 93.98 270 bottom
RP1  33x8  [EXB-2HV330JV]  62.23 32.77 180 top
RP2  33x8  [EXB-2HV330JV]  64.01 35.56 0 bottom
RP3  33x8  [EXB-2HV330JV]  59.44 35.56 0 bottom
S1  SwitchTactile3Pos  [SW3_4X2P5]  2.54 21.84 270 top
SW1  Rotary Switch  [SW-ND3FR10]  21.97 97.16 0 top
TP7  TP1mm  [TP_SMD1MMCIRCLE]  63.25 81.28 0 top
TP8  TP1mm  [TP_SMD1MMCIRCLE]  47.62 80.77 0 top
TP9  TP1mm  [TP_SMD1MMCIRCLE]  61.85 81.28 0 top
TP10  TP1mm  [TP_SMD1MMCIRCLE]  45.97 80.77 0 top
TP11  TP1mm  [TP_SMD1MMCIRCLE]  61.85 79.88 0 top
TP12  TP1mm  [TP_SMD1MMCIRCLE]  45.97 79.38 0 top
TP13  TP1mm  [TP_SMD1MMCIRCLE]  61.85 78.49 0 top
TP14  TP1mm  [TP_SMD1MMCIRCLE]  45.97 77.98 0 top
TP15  TP1mm  [TP_SMD1MMCIRCLE]  61.85 77.09 0 top
TP16  TP1mm  [TP_SMD1MMCIRCLE]  45.97 76.58 0 top
TP17  TP  [TH_TP_5002]  31.24 81.28 0 top
TP18  TP  [TH_TP_5002]  21.18 63.09 0 top
TP19  TP  [TH_TP_5002]  45.85 69.98 0 top
TP20  TP  [TH_TP_5002]  66.29 77.72 0 top
TP21  TP1mm  [TP_SMD1MMCIRCLE]  52.7 46.1 270 top
TP22  TP1mm  [TP_SMD1MMCIRCLE]  70.61 44.58 270 top
TP23  TP1mm  [TP_SMD1MMCIRCLE]  48.77 31.37 0 top
TP24  TESTPT1  [TP60C_SMD]  48.01 28.45 0 top
TP25  TESTPT1  [TP60C_SMD]  50.55 28.45 0 top
TP26  TP1mm  [TP_SMD1MMCIRCLE]  12.45 21.84 0 top
TP27  TP1mm  [TP_SMD1MMCIRCLE]  23.62 17.53 0 top
TP28  TP1mm  [TP_SMD1MMCIRCLE]  15.11 16.51 0 top
TP29  TP1mm  [TP_SMD1MMCIRCLE]  15.11 14.73 0 top
TP30  TP1mm  [TP_SMD1MMCIRCLE]  21.08 3.56 0 top
TP31  TP1mm  [TP_SMD1MMCIRCLE]  21.08 2.03 0 top
TP32  TP1mm  [TP_SMD1MMCIRCLE]  56.64 61.72 180 bottom
TP33  TP1mm  [TP_SMD1MMCIRCLE]  46.1 72.52 0 top
TP34  TP1mm  [TP_SMD1MMCIRCLE]  50.29 76.96 180 bottom
TP35  TP1mm  [TP_SMD1MMCIRCLE]  56.39 72.01 180 bottom
TP36  TP1mm  [TP_SMD1MMCIRCLE]  34.67 74.04 180 bottom
TP37  TP1mm  [TP_SMD1MMCIRCLE]  46.86 63.25 0 top
TP38  TP1mm  [TP_SMD1MMCIRCLE]  28.83 28.32 180 bottom
TP39  TP1mm  [TP_SMD1MMCIRCLE]  51.18 16.13 0 top
TP40  TP1mm  [TP_SMD1MMCIRCLE]  31.24 78.61 180 bottom
U1  M29W160EB  [TFBGA48]  21.97 86.23 90 top
U2  TLK110  [HTQFP_48PIN]  38.73 76.07 180 top
U3  TLK110  [HTQFP_48PIN]  55.12 76.07 180 top
U4  SN74CB3Q3306APWR  [PW8]  69.88 71.46 0 top
U5  SN74LVC1G08  [SM-SO-SC70-5]  48.39 71.5 180 top
U6  CAT24C256W  [SOIC8_208]  4.32 66.8 180 top
U7  SN74LVC1G32DCK  [SC70-5-43M]  45.34 66.67 0 top
U8  SN74LVC1G32DCK  [SC70-5-43M]  37.08 66.17 0 top
U9  SN74CBTLV3257RGY  [QFN4X3P5-16-39M]  30.73 65.79 270 top
U10  SN74LVC1G06DCK  [DCK5]  64.14 70.48 180 top
U11  SN74CBTLV3257RGY  [QFN4X3P5-16-39M]  41.91 62.87 270 top
U12  CDCE913  [TSSOP5X4-14-47M]  71.63 57.53 0 top
U13  SN74AUP2G08  [U_8_DCU]  24.38 46.74 0 top
U14  AM335X_15x15  [AM33XX_15X15]  39.37 44.45 180 top
U15  MT41J128M16JT-125  [BGA14X10-96]  62.1 44.45 0 top
U16  ISO1050  [SO8_W_DUB]  11.94 39.37 90 top
U17  W25Q64  [SOIC8_265]  29.21 29.84 180 top
U18  FT2232HL  [LQFP64_10X10]  17.02 28.96 0 top
U19  LM94022  [SC70-5]  40.13 28.96 0 top
U20  SN74LVC1G07  [DCK5]  51.31 21.46 180 top
U21  TPS5420D  [SOIC-8]  45.72 20.32 90 top
U22  TPS65910A3  [U_48_RSL]  17.65 9.65 270 top
U23  TPD4S012  [U_6_DRY]  4.06 6.73 180 top
U24  TPD6E001  [U_10_RSE]  17.83 2.7 90 top
U25  PCA9536DGK  [MSOP3X3-8-43M]  21.72 97.92 180 bottom
U26  SN74ALVCH16374DGV  [TVSOP-48]  22.73 72.77 90 bottom
U27  TPS76650  [SOIC_8]  22.1 57.4 180 bottom
U28  ISO1176T  [U_16_DW]  12.7 55.63 180 bottom
U29  TPS51200  [DRCPSO_10PIN]  68.33 34.54 90 bottom
U30  TPS71718  [SMDSC70-5]  32.89 24.89 180 bottom
U31  TPIC2810  [U_16_D]  56.64 24.77 180 bottom
U32  TPS78633  [SOT223_6PIN]  67.31 24 90 bottom
U33  93LC56B  [SOT23-6]  6.86 23.24 90 bottom
U34  TPS61041  [DBV5]  64.94 18.68 90 bottom
U35  SN65HVS882  [U_28_PWP]  56.26 14.35 180 bottom
U37  SN74LV244A  [TSSOP4X6-20]  57.02 59.56 0 top
U38  SN74LV244A  [TSSOP4X6-20]  49.91 59.56 0 bottom
Y1  25MHz  [SM_OSC_ABM3]  68.83 49.53 90 bottom
Y2  12MHz,+/-50ppm  [XTAL4_3P2X5SMD]  7.87 30.1 90 top
Y3  24MHz  [XTAL4_3P2X2P5_SMD]  38.23 56.83 0 bottom
Y4  32.768KHz MC-306  [MC-306]  46.48 28.96 0 bottom

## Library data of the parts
C1-C3 C5 C8-C12 C15 C34-C37 C43 C46 C56 C68 C69 C98 C106 C108-C114 C116 C119 C120 C123-C125 C130-C132 C134 C135 C137 C139 C142 C143 C148-C152 C155 C157 C160 C163 C164 C166 C169-C173 C175 C177 C181 C182 C187 C189 C190 C192-C194 C196 C197 C201-C204 C218 C219 C229 C236 C240 C254 C264 = 0.01uFCapacitor16V10%0402: User Part Number: USERPART#; Tolerance: TOLERANCE
C4 C6 C7 C13 C14 C16-C20 C32 C41 C55 C70-C75 C77-C80 C82 C83 C85-C88 C91 C93 C96 C159 C162 C167 C185 C188 C206-C208 C213 C214 C220 C221 C225 C227 C230-C232 C265 C269 C272 = 0.1uFCapacitor16V10%0402: User Part Number: USERPART#; Tolerance: TOLERANCE
C21 C22 = 1C_0.1uFCapacitor16V10%0402: User Part Number: USERPART#; Tolerance: TOLERANCE
C23 C27-C29 C38 C39 C47 C54 C61 C64 C65 C67 C81 C84 C92 C94 C95 C101 C102 C104 C107 C121 C154 C178 C179 C205 C209 C210 C212 C215 C251 C260 = 10uFCapacitor16V10%0805
C24 C191 = 4.7uFCapacitor16V20%Tant
C25 C26 C30 C31 C103 C105 C115 C117 C118 C122 C126-C129 C133 C136 C138 C140 C141 C144 C146 C147 C153 C156 C158 C161 C165 C168 C174 C176 C180 C183 = 0.1uFCapacitor6.3V10%0201
C33 C216 C273 = 0.001uFCapacitor50V5%0402: User Part Number: USERPART#; Tolerance: TOLERANCE
C40 C42 = 22pFCapacitor50V10%SMD0402: User Part Number: USERPART#; Tolerance: TOLERANCE
C44 C45 C57-C59 C66 C186 C257 C263 = 4.7uFCapacitor16V10%0603
C48 = 47uFCapacitor10V10%smd2917: User Part Number: P/N*; Tolerance: TOL*
C49 C50 C53 C244 C245 C261 = 2.2uFCapacitor6.3V20%smdX5R0402: User Part Number: USERPART#; Tolerance: TOLERANCE
C51 C52 C237 = 2.2uFCapacitor10V20%smd0402: User Part Number: USERPART#; Tolerance: TOLERANCE
C60 C97 C217 C234 C258 = 2.2uF16V10%SMD0805
C62 C63 = 2.2uFCapacitor35V20%smd0805
C76 C195 C198-C200 C223 C226 C228 C235 C238 C266 C268 C270 C271 = 1uFCapacitor10V10%0402: User Part Number: USERPART#; Tolerance: TOLERANCE
C89 C90 = 1C_18pFCapacitor50V5%0402: User Part Number: USERPART#; Tolerance: TOLERANCE
C99 C100 = 24pFCapacitor50V5%SMD0402: User Part Number: USERPART#; Tolerance: TOLERANCE
C145 C184 = 100pFCapacitor16V10%0402: User Part Number: USERPART#; Tolerance: TOLERANCE
C211 C222 = 18pFCapacitor50V5%0402: User Part Number: USERPART#; Tolerance: TOLERANCE
C224 = 4.7uFCapacitor6.3V20%smdX5R0603
C233 C248 C249 C262 = 10uFCapacitor50V10%1206
C239 C241 C246 C247 C250 C253 C256 C259 C267 = 0.022uFCapacitor16VX7Rsmd0402: User Part Number: USERPART#; Tolerance: TOLERANCE
C242 C243 = 0.1uFCapacitor50V10%0402: User Part Number: USERPART#; Tolerance: TOLERANCE
C252 = 1uFCapacitor50V10%0603
C255 = 10pFCapacitor50V1%smd0402: User Part Number: USERPART#; Tolerance: TOLERANCE
C275 C277 = 1C_0.01uFCapacitor16V10%0402: User Part Number: USERPART#; Tolerance: TOLERANCE
D1 D2 = LED_Tricolor_RedGreenYellow
D3 D6-D10 D12 D14-D16 = LED_Green
D4 D5 = LED_Yellow
D11 D13 D20 = Diode_500mA20V
D17 = Diode_3ARect_rev40V
D18 = Diode_MBRS140T3
D19 = Diode_SMCJ26CA
F1 = Fuse_4A
FB2 FB3 FB9-FB13 = FerBead_180ohm200mA
J1 J2 = 2J_ConnectorRJ45_10_100MbAMDIX
J3 = Header9x2_0.1in_Female
J4 = Header15x2_0.1in_Female
J5 J8 = Header_1.27mm_3pin
J6 J7 J10 = Header_1.27mm_2pin
J9 = Conn_DSUB9F
J11 = Conn_PwrJack_RAPC722
J12 = Conn_LeadScrewDown_2pin
J13 = Conn_MicroUSBAB
J14 = Header20x2_0.1in_Female
J15 = Header10x2_CJTAG
J16 = Conn_microSD_8: User Part Number: X; Tolerance: X
J17 = Conn_14pin_0.5mm_FPC: User Part Number: PRT#; Tolerance: TOL*
J18 J19 = 2H_Header_3x1
L1 = DA2304-ALB
L2 = 2.2uHInductor20%1Asmd
L3 = 68uHInductor20%1.4Asmd
L4 L5 L7 = 2.2uHInductor10%2.6Asmd
L6 = ACM2012
MH1-MH4 = Mounthole_3mm
Q1-Q4 = NPN_DMC564040R
R1-R6 R89 R93 R94 R98 R128 R130 R131 = 330ohm1/16W5%smd0402
R7 R8 R15 R16 R27-R34 R61 R90 R92 R95 R97 R110 R112-R114 R124 R129 R134 R135 R174 R196 R205 R207 = 2.2KOhmResistor1/16W0402
R9 R10 = 1R_4.87KOhmResistor1/16W0402
R11 R62 R63 R178 R184 R191 R195 = 10KOhmResistor1/10W1%0402
R12 R13 R179-R182 R186 = 33ohmResistor1/16W5%0402
R14 R24 R25 R70 R71 R137 = 4.7KOhmResistor1/16W0402
R17 R22 R23 R26 R35 R36 R60 R64 R69 R72 R91 R96 R105 R126 R139 R142 R146 R147 R149 R150 R156 R175 R190 R192 R194 R198 R201-R204 R209 R222-R225 R228-R230 = ZeroOhmResistor1/16W0402
R18 R19 R145 R148 R243 R244 = 1R_2.2KOhmResistor1/16W0402
R20 = 100ohm1/10W1%SMD0402
R21 R65 R67 R75 R101 R111 R125 R141 R187 R197 R199 R200 R206 R210 R211 R231 R233-R237 = 10KOhmResistor1/16W0402
R37 R44 R45 R50 R54 R55 R188 = 1R_10KOhmResistor1/10W1%0402
R38 R43 R46-R49 R51-R53 R56 R57 R152 R153 R157-R171 R176 = 100KOhmResistor1/16W0402
R39 R277 R278 = 1R_4.7KOhmResistor1/16W0402
R40 R41 R59 R87 R88 R99 R100 R102-R104 R106-R109 R115 R127 = 1KOhmResistor1/16W0402
R42 R144 R154 = 1R_33ohmResistor1/16W5%0402
R58 = 22OhmResistor1/16W1%0402: signal model: 22OHMRESISTOR1/16W1%0402_SM-735_22
R66 = 3.24KOhmResistor1/10W1%0402
R68 R74 R79-R81 R83 R84 R226 = 1.2Kohm1/3W1%SMDMELF0102
R73 R76-R78 R85 R86 R213-R218 = ZeroOhmResistor1/16W0603
R82 = 25Kohm1/10W0.1%smd0603
R116-R123 R185 = 49.9OhmResistor1/16W0402
R132 R133 R136 R140 R143 R151 R155 R173 R208 = 150ohm1/16W1%SMD0402
R138 = ZeroOhmResistor1/16W0402: signal model: ZEROOHMRESISTOR1/16W0402_SM-735_0
R172 = 1MOhmResistor1/16W0402: signal model: 33OHMRESISTOR1_16W5_0402_SM_735_33
R177 = 1KOhmResistor1/16W0402: signal model: 33OHMRESISTOR1_16W5_0402_SM_735_33
R183 = 240OhmResistor1/10W1%0402
R189 = 1R_4.75KohmResistor1/16W1%0402
R193 = 12.1KohmResistor1/16W1%0402
R212 R219 = 0.05ohm0.5W1%Sense1206
R220 = 1.62MOhmResistor1/16W0402
R221 = 180KOhmResistor1/16W0402
R227 = 49.9ohm1/3W1%SMDMELF0102
R232 = 392KOhmResistor1/10W1%0402
R238 = 1R_120ohm1/16W1%smd0402
R239-R242 R279 R280 = 1R_ZeroOhmResistor1/16W0603
RP1-RP3 = 33ohmx8_1/16W5%smd
S1 = SwitchTactile3pos_smd
SW1 = SwitchDIPRotaries_smd
TP7-TP16 TP21-TP23 TP26-TP40 = Testpoint_SMD1mmCircle
TP17-TP20 = TestPointThroughHole
TP24 TP25 = TESTPT1
U1 = M29W160G: User Part Number: PRT#; Tolerance: TOL*
U2 U3 = TLK110
U4 = SN74CB3Q3306APW
U5 = SN74LVC1G08DCKT_SC70
U6 = CAT24C256W
U7 U8 = SN74LVC1G32DCK
U9 U11 = SN74CBTLV3257RGY
U10 = SN74LVC1G06DCK: Tolerance: TOL; User Part Number: PART#
U12 = 1A_CDCE913
U13 = SN74AUP2G08
U14 = AM335X_15mmx15mm
U15 = MT41J128M16JT-125
U16 = ISO1050
U17 = W25Q64
U18 = FT2232_0
U19 = LM94022
U20 = SN74LVC1G07: Tolerance: TOL; User Part Number: PART#
U21 = TPS5420D
U22 = TPS65910A3
U23 = TPD4S012
U24 = TPD6E001RSE
U25 = PCA9536
U26 = SN74ALVCH16374DGVR
U27 = TPS76650
U28 = ISO1176T
U29 = TPS51200
U30 = TPS71718
U31 = TPIC2810
U32 = TPS78633DCQ
U33 = 93C46B_SSOT23-6
U34 = TPS61041DBV
U35 = SN65HVS882
U37 U38 = 1A_SN74LV244APWRG3
Y1 = Crystal25MHzABM3
Y2 = Crystal12MHZ_ECS-120-20-30B: Tolerance: TOL*; User Part Number: P/N*
Y3 = Crystal24MHz18PFsmd
Y4 = Crystal_SMD32_768kHz

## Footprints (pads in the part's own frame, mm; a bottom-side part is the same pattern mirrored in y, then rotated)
7343
  rect 2.54x2.413 smd: 1(-3.2,0) 2(3.2,0)
ACM2012H
  rect 0.75x0.35 smd: 1(-0.975,0.425) 2(-0.975,-0.425) 3(0.975,-0.425) 4(0.975,0.425)
AM33XX_15X15
  round 0.356 smd: A1(-6.8,6.8) A2(-6,6.8) A3(-5.2,6.8) A4(-4.4,6.8) A5(-3.6,6.8) A6(-2.8,6.8) A7(-2,6.8) A8(-1.2,6.8) A9(-0.4,6.8) A10(0.4,6.8) A11(1.2,6.8) A12(2,6.8) A13(2.8,6.8) A14(3.6,6.8) A15(4.4,6.8) A16(5.2,6.8) A17(6,6.8) A18(6.8,6.8) B1(-6.8,6) B2(-6,6) B3(-5.2,6) B4(-4.4,6) B5(-3.6,6) B6(-2.8,6) B7(-2,6) B8(-1.2,6) B9(-0.4,6) B10(0.4,6) B11(1.2,6) B12(2,6) B13(2.8,6) B14(3.6,6) B15(4.4,6) B16(5.2,6) B17(6,6) B18(6.8,6) C1(-6.8,5.2) C2(-6,5.2) C3(-5.2,5.2) C4(-4.4,5.2) C5(-3.6,5.2) C6(-2.8,5.2) C7(-2,5.2) C8(-1.2,5.2) C9(-0.4,5.2) C10(0.4,5.2) C11(1.2,5.2) C12(2,5.2) C13(2.8,5.2) C14(3.6,5.2) C15(4.4,5.2) C16(5.2,5.2) C17(6,5.2) C18(6.8,5.2) D1(-6.8,4.4) D2(-6,4.4) D3(-5.2,4.4) D4(-4.4,4.4) D5(-3.6,4.4) D6(-2.8,4.4) D7(-2,4.4) D8(-1.2,4.4) D9(-0.4,4.4) D10(0.4,4.4) D11(1.2,4.4) D12(2,4.4) D13(2.8,4.4) D14(3.6,4.4) D15(4.4,4.4) D16(5.2,4.4) D17(6,4.4) D18(6.8,4.4) E1(-6.8,3.6) E2(-6,3.6) E3(-5.2,3.6) E4(-4.4,3.6) E5(-3.6,3.6) E6(-2.8,3.6) E7(-2,3.6) E8(-1.2,3.6) E9(-0.4,3.6) E10(0.4,3.6) E11(1.2,3.6) E12(2,3.6) E13(2.8,3.6) E14(3.6,3.6) E15(4.4,3.6) E16(5.2,3.6) E17(6,3.6) E18(6.8,3.6) F1(-6.8,2.8) F2(-6,2.8) F3(-5.2,2.8) F4(-4.4,2.8) F5(-3.6,2.8) F6(-2.8,2.8) F7(-2,2.8) F8(-1.2,2.8) F9(-0.4,2.8) F10(0.4,2.8) F11(1.2,2.8) F12(2,2.8) F13(2.8,2.8) F14(3.6,2.8) F15(4.4,2.8) F16(5.2,2.8) F17(6,2.8) F18(6.8,2.8) G1(-6.8,2) G2(-6,2) G3(-5.2,2) G4(-4.4,2) G5(-3.6,2) G6(-2.8,2) G7(-2,2) G8(-1.2,2) G9(-0.4,2) G10(0.4,2) G11(1.2,2) G12(2,2) G13(2.8,2) G14(3.6,2) G15(4.4,2) G16(5.2,2) G17(6,2) G18(6.8,2) H1(-6.8,1.2) H2(-6,1.2) H3(-5.2,1.2) H4(-4.4,1.2) H5(-3.6,1.2) H6(-2.8,1.2) H7(-2,1.2) H8(-1.2,1.2) H9(-0.4,1.2) H10(0.4,1.2) H11(1.2,1.2) H12(2,1.2) H13(2.8,1.2) H14(3.6,1.2) H15(4.4,1.2) H16(5.2,1.2) H17(6,1.2) H18(6.8,1.2) J1(-6.8,0.4) J2(-6,0.4) J3(-5.2,0.4) J4(-4.4,0.4) J5(-3.6,0.4) J6(-2.8,0.4) J7(-2,0.4) J8(-1.2,0.4) J9(-0.4,0.4) J10(0.4,0.4) J11(1.2,0.4) J12(2,0.4) J13(2.8,0.4) J14(3.6,0.4) J15(4.4,0.4) J16(5.2,0.4) J17(6,0.4) J18(6.8,0.4) K1(-6.8,-0.4) K2(-6,-0.4) K3(-5.2,-0.4) K4(-4.4,-0.4) K5(-3.6,-0.4) K6(-2.8,-0.4) K7(-2,-0.4) K8(-1.2,-0.4) K9(-0.4,-0.4) K10(0.4,-0.4) K11(1.2,-0.4) K12(2,-0.4) K13(2.8,-0.4) K14(3.6,-0.4) K15(4.4,-0.4) K16(5.2,-0.4) K17(6,-0.4) K18(6.8,-0.4) L1(-6.8,-1.2) L2(-6,-1.2) L3(-5.2,-1.2) L4(-4.4,-1.2) L5(-3.6,-1.2) L6(-2.8,-1.2) L7(-2,-1.2) L8(-1.2,-1.2) L9(-0.4,-1.2) L10(0.4,-1.2) L11(1.2,-1.2) L12(2,-1.2) L13(2.8,-1.2) L14(3.6,-1.2) L15(4.4,-1.2) L16(5.2,-1.2) L17(6,-1.2) L18(6.8,-1.2) M1(-6.8,-2) M2(-6,-2) M3(-5.2,-2) M4(-4.4,-2) M5(-3.6,-2) M6(-2.8,-2) M7(-2,-2) M8(-1.2,-2) M9(-0.4,-2) M10(0.4,-2) M11(1.2,-2) M12(2,-2) M13(2.8,-2) M14(3.6,-2) M15(4.4,-2) M16(5.2,-2) M17(6,-2) M18(6.8,-2) N1(-6.8,-2.8) N2(-6,-2.8) N3(-5.2,-2.8) N4(-4.4,-2.8) N5(-3.6,-2.8) N6(-2.8,-2.8) N7(-2,-2.8) N8(-1.2,-2.8) N9(-0.4,-2.8) N10(0.4,-2.8) N11(1.2,-2.8) N12(2,-2.8) N13(2.8,-2.8) N14(3.6,-2.8) N15(4.4,-2.8) N16(5.2,-2.8) N17(6,-2.8) N18(6.8,-2.8) P1(-6.8,-3.6) P2(-6,-3.6) P3(-5.2,-3.6) P4(-4.4,-3.6) P5(-3.6,-3.6) P6(-2.8,-3.6) P7(-2,-3.6) P8(-1.2,-3.6) P9(-0.4,-3.6) P10(0.4,-3.6) P11(1.2,-3.6) P12(2,-3.6) P13(2.8,-3.6) P14(3.6,-3.6) P15(4.4,-3.6) P16(5.2,-3.6) P17(6,-3.6) P18(6.8,-3.6) R1(-6.8,-4.4) R2(-6,-4.4) R3(-5.2,-4.4) R4(-4.4,-4.4) R5(-3.6,-4.4) R6(-2.8,-4.4) R7(-2,-4.4) R8(-1.2,-4.4) R9(-0.4,-4.4) R10(0.4,-4.4) R11(1.2,-4.4) R12(2,-4.4) R13(2.8,-4.4) R14(3.6,-4.4) R15(4.4,-4.4) R16(5.2,-4.4) R17(6,-4.4) R18(6.8,-4.4) T1(-6.8,-5.2) T2(-6,-5.2) T3(-5.2,-5.2) T4(-4.4,-5.2) T5(-3.6,-5.2) T6(-2.8,-5.2) T7(-2,-5.2) T8(-1.2,-5.2) T9(-0.4,-5.2) T10(0.4,-5.2) T11(1.2,-5.2) T12(2,-5.2) T13(2.8,-5.2) T14(3.6,-5.2) T15(4.4,-5.2) T16(5.2,-5.2) T17(6,-5.2) T18(6.8,-5.2) U1(-6.8,-6) U2(-6,-6) U3(-5.2,-6) U4(-4.4,-6) U5(-3.6,-6) U6(-2.8,-6) U7(-2,-6) U8(-1.2,-6) U9(-0.4,-6) U10(0.4,-6) U11(1.2,-6) U12(2,-6) U13(2.8,-6) U14(3.6,-6) U15(4.4,-6) U16(5.2,-6) U17(6,-6) U18(6.8,-6) V1(-6.8,-6.8) V2(-6,-6.8) V3(-5.2,-6.8) V4(-4.4,-6.8) V5(-3.6,-6.8) V6(-2.8,-6.8) V7(-2,-6.8) V8(-1.2,-6.8) V9(-0.4,-6.8) V10(0.4,-6.8) V11(1.2,-6.8) V12(2,-6.8) V13(2.8,-6.8) V14(3.6,-6.8) V15(4.4,-6.8) V16(5.2,-6.8) V17(6,-6.8) V18(6.8,-6.8)
BGA14X10-96
  round 0.35 smd: A1(-3.2,6) A2(-2.4,6) A3(-1.6,6) A7(1.6,6) A8(2.4,6) A9(3.2,6) B1(-3.2,5.2) B2(-2.4,5.2) B3(-1.6,5.2) B7(1.6,5.2) B8(2.4,5.2) B9(3.2,5.2) C1(-3.2,4.4) C2(-2.4,4.4) C3(-1.6,4.4) C7(1.6,4.4) C8(2.4,4.4) C9(3.2,4.4) D1(-3.2,3.6) D2(-2.4,3.6) D3(-1.6,3.6) D7(1.6,3.6) D8(2.4,3.6) D9(3.2,3.6) E1(-3.2,2.8) E2(-2.4,2.8) E3(-1.6,2.8) E7(1.6,2.8) E8(2.4,2.8) E9(3.2,2.8) F1(-3.2,2) F2(-2.4,2) F3(-1.6,2) F7(1.6,2) F8(2.4,2) F9(3.2,2) G1(-3.2,1.2) G2(-2.4,1.2) G3(-1.6,1.2) G7(1.6,1.2) G8(2.4,1.2) G9(3.2,1.2) H1(-3.2,0.4) H2(-2.4,0.4) H3(-1.6,0.4) H7(1.6,0.4) H8(2.4,0.4) H9(3.2,0.4) J1(-3.2,-0.4) J2(-2.4,-0.4) J3(-1.6,-0.4) J7(1.6,-0.4) J8(2.4,-0.4) J9(3.2,-0.4) K1(-3.2,-1.2) K2(-2.4,-1.2) K3(-1.6,-1.2) K7(1.6,-1.2) K8(2.4,-1.2) K9(3.2,-1.2) L1(-3.2,-2) L2(-2.4,-2) L3(-1.6,-2) L7(1.6,-2) L8(2.4,-2) L9(3.2,-2) M1(-3.2,-2.8) M2(-2.4,-2.8) M3(-1.6,-2.8) M7(1.6,-2.8) M8(2.4,-2.8) M9(3.2,-2.8) N1(-3.2,-3.6) N2(-2.4,-3.6) N3(-1.6,-3.6) N7(1.6,-3.6) N8(2.4,-3.6) N9(3.2,-3.6) P1(-3.2,-4.4) P2(-2.4,-4.4) P3(-1.6,-4.4) P7(1.6,-4.4) P8(2.4,-4.4) P9(3.2,-4.4) R1(-3.2,-5.2) R2(-2.4,-5.2) R3(-1.6,-5.2) R7(1.6,-5.2) R8(2.4,-5.2) R9(3.2,-5.2) T1(-3.2,-6) T2(-2.4,-6) T3(-1.6,-6) T7(1.6,-6) T8(2.4,-6) T9(3.2,-6)
